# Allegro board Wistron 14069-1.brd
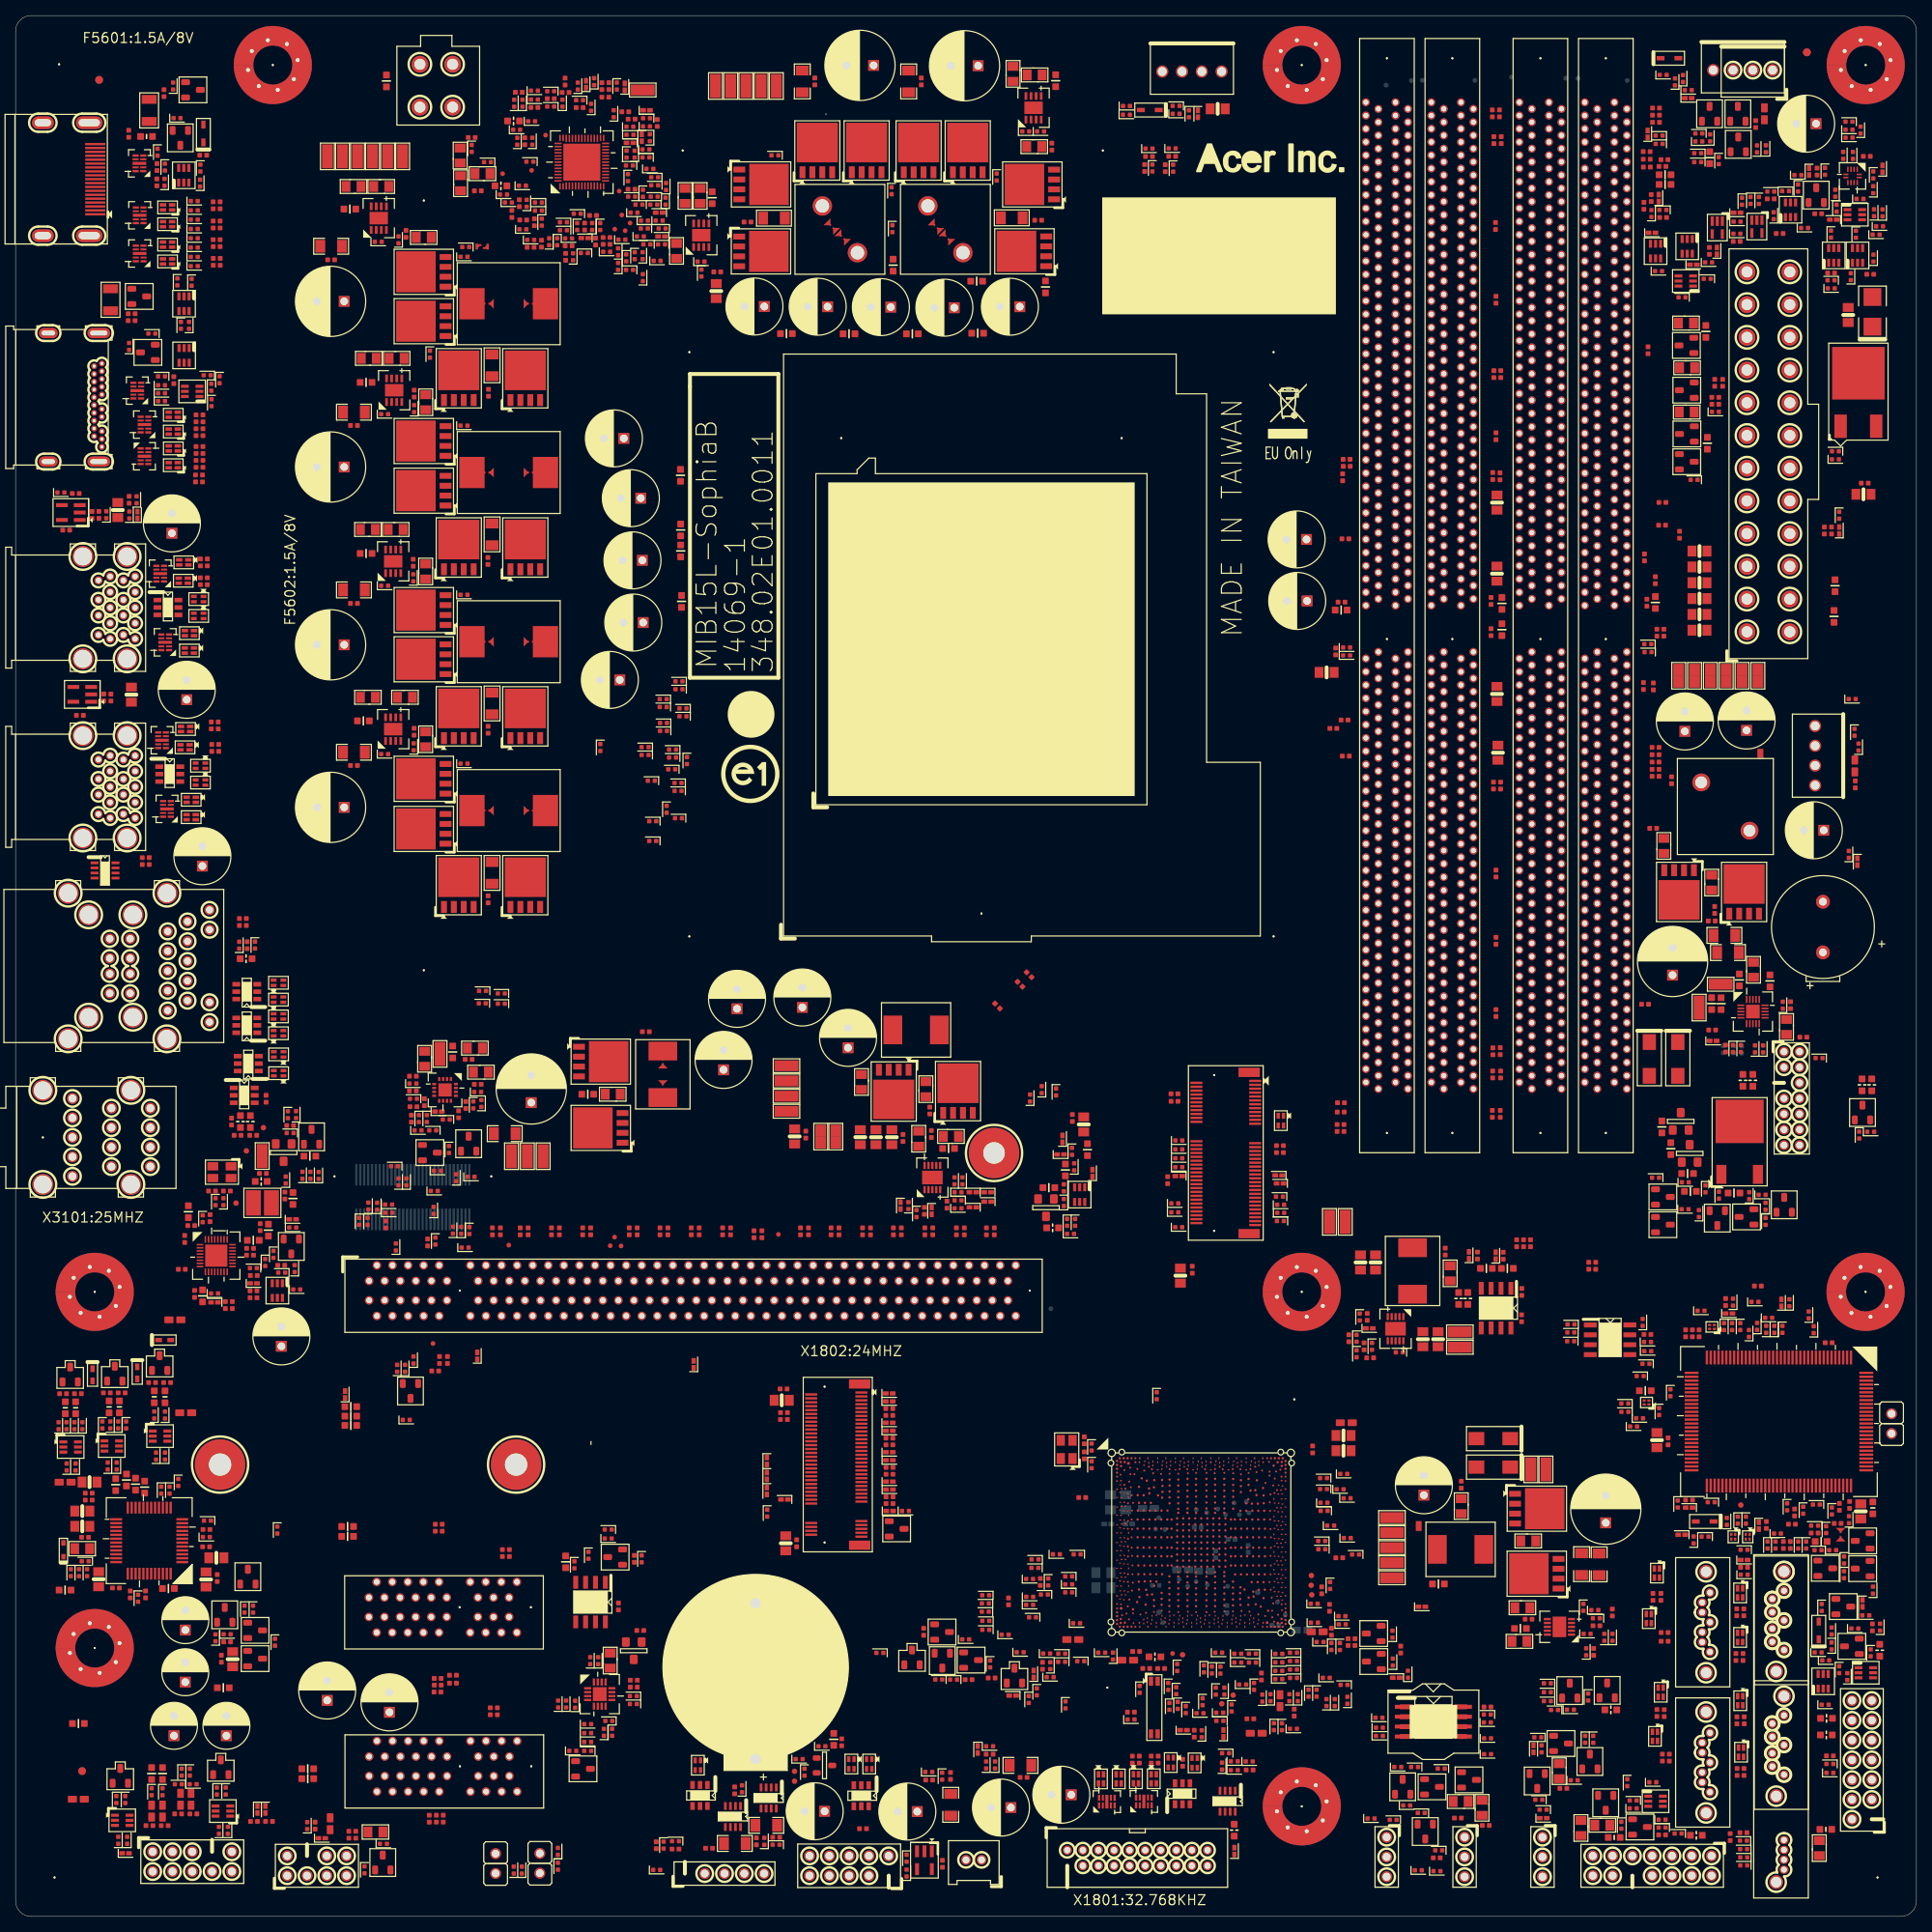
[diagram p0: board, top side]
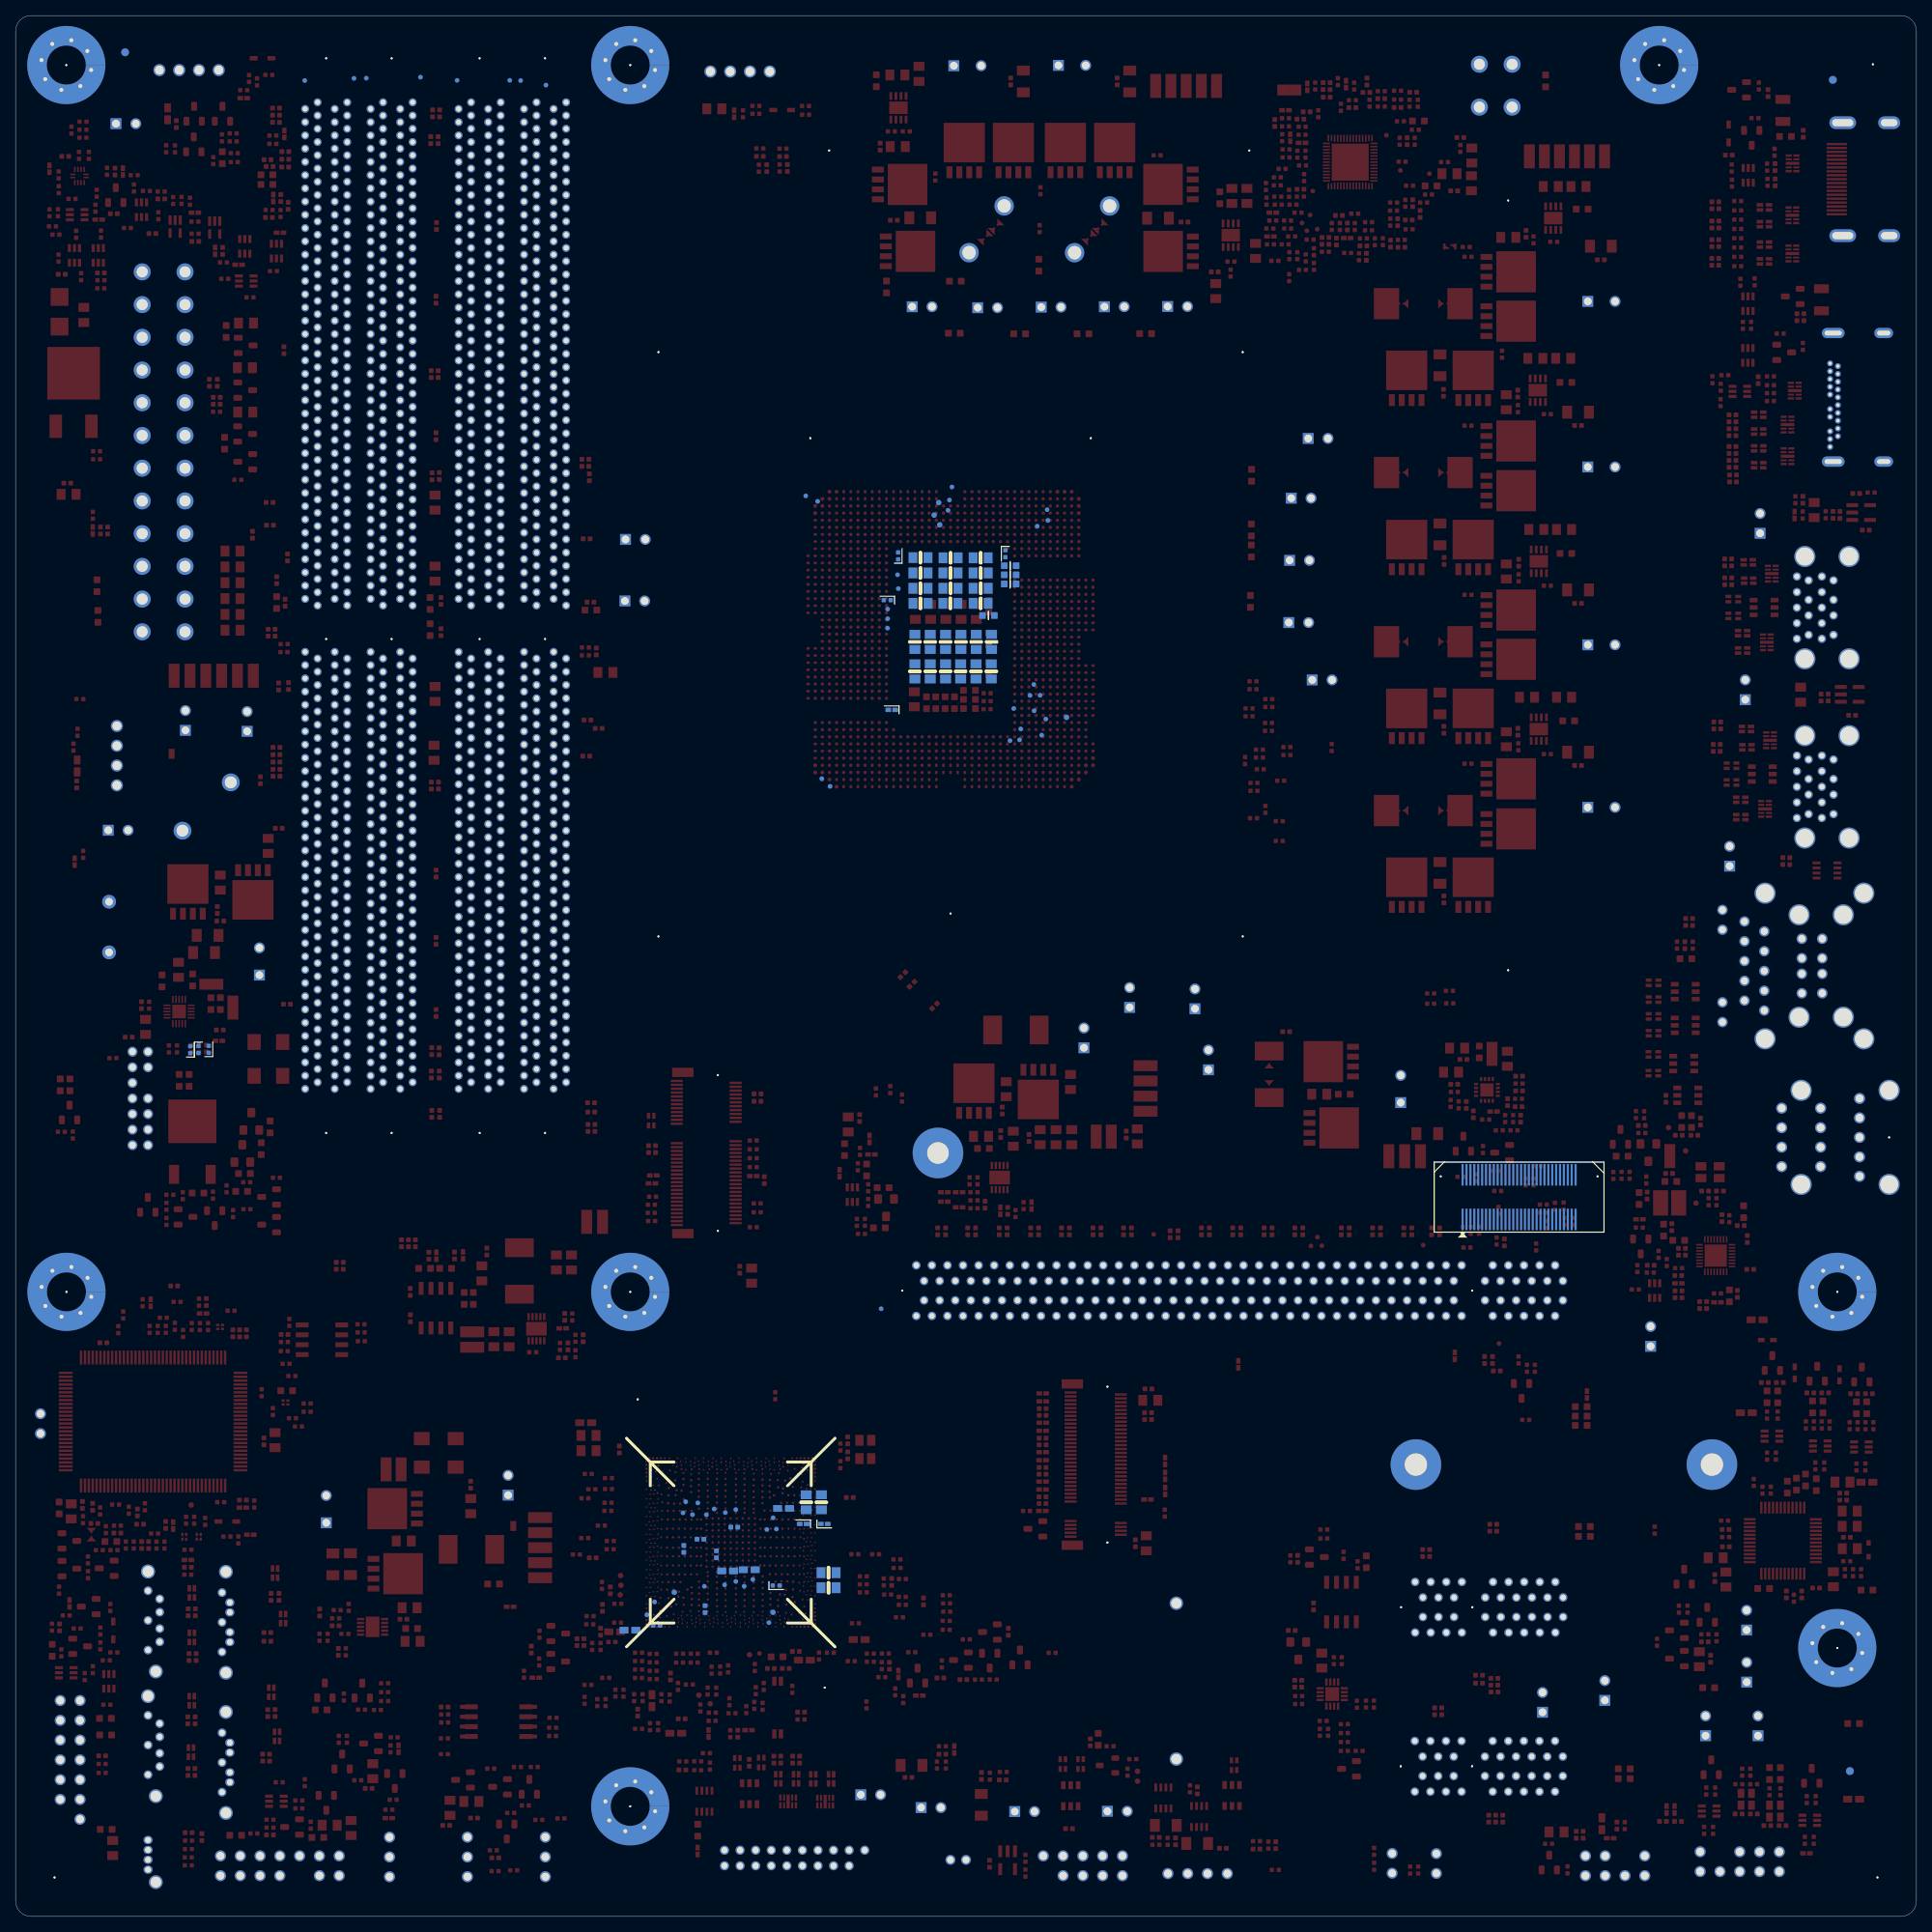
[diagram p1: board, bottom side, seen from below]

Outline 244 x 244 mm; copper layers: TOP, L2, L3, BOTTOM. Coordinates in mm from the lower left corner of the outline.
Outline path: 0,242 0,2 arc(0.59,0.59) 2,0 242,0 arc(243.41,0.59) 244,2 244,242 arc(243.41,243.41) 242,244 2,244 arc(0.59,243.41) 0,242

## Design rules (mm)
constraint set DEFAULT: min track width 0.127, pair gap 0.102
net group DP_AUX_CON_N: nets DP_AUX_CPU_N DP_AUX_CPU_N_C
net group DP_AUX_CON_P: nets DP_AUX_CPU_P DP_AUX_CPU_P_C
net group DP_DATA_CON_N0: nets DP_DATA_CPU_N0 DP_DATA_N0
net group DP_DATA_CON_N1: nets DP_DATA_CPU_N1 DP_DATA_N1
net group DP_DATA_CON_N2: nets DP_DATA_CPU_N2 DP_DATA_N2
net group DP_DATA_CON_N3: nets DP_DATA_CPU_N3 DP_DATA_N3
net group DP_DATA_CON_P0: nets DP_DATA_CPU_P0 DP_DATA_P0
net group DP_DATA_CON_P1: nets DP_DATA_CPU_P1 DP_DATA_P1
net group DP_DATA_CON_P2: nets DP_DATA_CPU_P2 DP_DATA_P2
net group DP_DATA_CON_P3: nets DP_DATA_CPU_P3 DP_DATA_P3
net group FAN_SYS_POWER: nets SYS_FAN_3P_POWER SYS_FAN_3P_POWER_2
net group HDA_BITCLK_CODEC: nets HDA_BITCLK_CODEC HDA_BITCLK_PCH
net group HDA_RST#_CODEC: nets HDA_RST#_CODEC HDA_RST#_PCH
net group HDA_SDIN0_CODEC: nets HDA_SDIN0_CODEC HDA_SDIN0_PCH
net group HDA_SDOUT_CODEC: nets HDA_SDOUT_CODEC HDA_SDOUT_PCH
net group HDA_SYNC_CODEC: nets HDA_SYNC_CODEC HDA_SYNC_PCH
net group HDMI_CLK_CON: nets HDMI_CLK_CON HDMI_CLK_PCH
net group HDMI_DATA_CMC_N0: nets HDMI_DATA_CMC_N0 HDMI_DATA_CPU_N0
net group HDMI_DATA_CMC_N1: nets HDMI_DATA_CMC_N1 HDMI_DATA_CPU_N1
net group HDMI_DATA_CMC_N2: nets HDMI_DATA_CMC_N2 HDMI_DATA_CPU_N2
net group HDMI_DATA_CMC_N3: nets HDMI_DATA_CMC_N3 HDMI_DATA_CPU_N3
net group HDMI_DATA_CMC_P0: nets HDMI_DATA_CMC_P0 HDMI_DATA_CPU_P0
net group HDMI_DATA_CMC_P1: nets HDMI_DATA_CMC_P1 HDMI_DATA_CPU_P1
net group HDMI_DATA_CMC_P2: nets HDMI_DATA_CMC_P2 HDMI_DATA_CPU_P2
net group HDMI_DATA_CMC_P3: nets HDMI_DATA_CMC_P3 HDMI_DATA_CPU_P3
net group HDMI_DATA_CON: nets HDMI_DATA_CON HDMI_DATA_PCH
net group HDMI_DDSP_D: nets DDSP_D_TX_N0 DDSP_D_TX_N2
net group LAN_MDI_CON_N0: nets LAN_MDI_CON_N0 LAN_MDI_LAN_N0
net group LAN_MDI_CON_N1: nets LAN_MDI_CON_N1 LAN_MDI_LAN_N1
net group LAN_MDI_CON_N2: nets LAN_MDI_CON_N2 LAN_MDI_LAN_N2
net group LAN_MDI_CON_N3: nets LAN_MDI_CON_N3 LAN_MDI_LAN_N3
net group LAN_MDI_CON_P0: nets LAN_MDI_CON_P0 LAN_MDI_LAN_P0
net group LAN_MDI_CON_P1: nets LAN_MDI_CON_P1 LAN_MDI_LAN_P1
net group LAN_MDI_CON_P2: nets LAN_MDI_CON_P2 LAN_MDI_LAN_P2
net group LAN_MDI_CON_P3: nets LAN_MDI_CON_P3 LAN_MDI_LAN_P3
net group PCIE_RX_CON_N9: nets PCIE_RX_CON_N9 PCIE_RX_PCH_N9
net group PCIE_RX_CON_N10: nets PCIE_RX_CON_N10 PCIE_RX_PCH_N10
net group PCIE_RX_CON_N11: nets PCIE_RX_CON_N11 PCIE_RX_PCH_N11
net group PCIE_RX_CON_P9: nets PCIE_RX_CON_P9 PCIE_RX_PCH_P9
net group PCIE_RX_CON_P10: nets PCIE_RX_CON_P10 PCIE_RX_PCH_P10
net group PCIE_RX_CON_P11: nets PCIE_RX_CON_P11 PCIE_RX_PCH_P11
net group PCIE_RX_LAN_N5: nets PCIE_RX_LAN_N5 PCIE_RX_PCH_N5
net group PCIE_RX_LAN_P5: nets PCIE_RX_LAN_P5 PCIE_RX_PCH_P5
net group PCIE_TX_CON_N6: nets PCIE_TX_CON_N6 PCIE_TX_PCH_N6
net group PCIE_TX_CON_N7: nets PCIE_TX_CON_N7 PCIE_TX_PCH_N7
net group PCIE_TX_CON_N8: nets PCIE_TX_CON_N8 PCIE_TX_PCH_N8
net group PCIE_TX_CON_N9: nets PCIE_TX_CON_N9 PCIE_TX_PCH_N9
net group PCIE_TX_CON_N10: nets PCIE_TX_CON_N10 PCIE_TX_PCH_N10
net group PCIE_TX_CON_N11: nets PCIE_TX_CON_N11 PCIE_TX_PCH_N11
net group PCIE_TX_CON_N12: nets PCIE_TX_CON_N12 PCIE_TX_PCH_N12
net group PCIE_TX_CON_P6: nets PCIE_TX_CON_P6 PCIE_TX_PCH_P6
net group PCIE_TX_CON_P7: nets PCIE_TX_CON_P7 PCIE_TX_PCH_P7
net group PCIE_TX_CON_P8: nets PCIE_TX_CON_P8 PCIE_TX_PCH_P8
net group PCIE_TX_CON_P9: nets PCIE_TX_CON_P9 PCIE_TX_PCH_P9
net group PCIE_TX_CON_P10: nets PCIE_TX_CON_P10 PCIE_TX_PCH_P10
net group PCIE_TX_CON_P11: nets PCIE_TX_CON_P11 PCIE_TX_PCH_P11
net group PCIE_TX_CON_P12: nets PCIE_TX_CON_P12 PCIE_TX_PCH_P12
net group PCIE_TX_LAN_N5: nets PCIE_TX_LAN_N5 PCIE_TX_PCH_N5
net group PCIE_TX_LAN_P5: nets PCIE_TX_LAN_P5 PCIE_TX_PCH_P5
net group PEG_RCOMP: nets PEG_RCOMPN_CPU PEG_RCOMPP_CPU
net group PEG_TX_CON_N0: nets PEG_TX_CON_N0 PEG_TX_CPU_N0
net group PEG_TX_CON_N1: nets PEG_TX_CON_N1 PEG_TX_CPU_N1
net group PEG_TX_CON_N2: nets PEG_TX_CON_N2 PEG_TX_CPU_N2
net group PEG_TX_CON_N3: nets PEG_TX_CON_N3 PEG_TX_CPU_N3
net group PEG_TX_CON_N4: nets PEG_TX_CON_N4 PEG_TX_CPU_N4
net group PEG_TX_CON_N5: nets PEG_TX_CON_N5 PEG_TX_CPU_N5
net group PEG_TX_CON_N6: nets PEG_TX_CON_N6 PEG_TX_CPU_N6
net group PEG_TX_CON_N7: nets PEG_TX_CON_N7 PEG_TX_CPU_N7
net group PEG_TX_CON_N8: nets PEG_TX_CON_N8 PEG_TX_CPU_N8
net group PEG_TX_CON_N9: nets PEG_TX_CON_N9 PEG_TX_CPU_N9
net group PEG_TX_CON_N10: nets PEG_TX_CON_N10 PEG_TX_CPU_N10
net group PEG_TX_CON_N11: nets PEG_TX_CON_N11 PEG_TX_CPU_N11
net group PEG_TX_CON_N12: nets PEG_TX_CON_N12 PEG_TX_CPU_N12
net group PEG_TX_CON_N13: nets PEG_TX_CON_N13 PEG_TX_CPU_N13
net group PEG_TX_CON_N14: nets PEG_TX_CON_N14 PEG_TX_CPU_N14
net group PEG_TX_CON_N15: nets PEG_TX_CON_N15 PEG_TX_CPU_N15
net group PEG_TX_CON_P0: nets PEG_TX_CON_P0 PEG_TX_CPU_P0
net group PEG_TX_CON_P1: nets PEG_TX_CON_P1 PEG_TX_CPU_P1
net group PEG_TX_CON_P2: nets PEG_TX_CON_P2 PEG_TX_CPU_P2
net group PEG_TX_CON_P3: nets PEG_TX_CON_P3 PEG_TX_CPU_P3
net group PEG_TX_CON_P4: nets PEG_TX_CON_P4 PEG_TX_CPU_P4
net group PEG_TX_CON_P5: nets PEG_TX_CON_P5 PEG_TX_CPU_P5
net group PEG_TX_CON_P6: nets PEG_TX_CON_P6 PEG_TX_CPU_P6
net group PEG_TX_CON_P7: nets PEG_TX_CON_P7 PEG_TX_CPU_P7
net group PEG_TX_CON_P8: nets PEG_TX_CON_P8 PEG_TX_CPU_P8
net group PEG_TX_CON_P9: nets PEG_TX_CON_P9 PEG_TX_CPU_P9
net group PEG_TX_CON_P10: nets PEG_TX_CON_P10 PEG_TX_CPU_P10
net group PEG_TX_CON_P11: nets PEG_TX_CON_P11 PEG_TX_CPU_P11
net group PEG_TX_CON_P12: nets PEG_TX_CON_P12 PEG_TX_CPU_P12
net group PEG_TX_CON_P13: nets PEG_TX_CON_P13 PEG_TX_CPU_P13
net group PEG_TX_CON_P14: nets PEG_TX_CON_P14 PEG_TX_CPU_P14
net group PEG_TX_CON_P15: nets PEG_TX_CON_P15 PEG_TX_CPU_P15
net group POWER_80_12: nets 5V_AUX_WPWR PWR_2D5V_PVIN
net group PWR_RT3607_RGNDA: nets PWR_RT3607_RGNDA VSSGT_SENSE
net group PWR_VCCSA_FB: nets PWR_VCCSA_FB VCCSA_SENSE
net group SIO_VREF: nets SYS_TMPIN VRD_TMPIN
net group SPI_CLK_PCH: nets SPI_CLK_PCH SPI_CLK_ROM
net group SPI_HOLD_PCH: nets SPI_HOLD_PCH SPI_HOLD_ROM
net group SPI_S: nets SPI_CS_PCH_N0 SPI_WP_ROM_PLL
net group SPI_SI_PCH: nets SPI_SI_PCH SPI_SI_ROM
net group SPI_SO_PCH: nets SPI_SO_PCH SPI_SO_ROM
net group USB30_RX_CON_N1: nets USB30_RX_CON_N1 USB30_RX_PCH_N1
net group USB30_RX_CON_N2: nets USB30_RX_CON_N2 USB30_RX_PCH_N2
net group USB30_RX_CON_N3: nets USB30_RX_CON_N3 USB30_RX_PCH_N3
net group USB30_RX_CON_N4: nets USB30_RX_CON_N4 USB30_RX_PCH_N4
net group USB30_RX_CON_N5: nets USB30_RX_CON_N5 USB30_RX_PCH_N5
net group USB30_RX_CON_N6: nets USB30_RX_CON_N6 USB30_RX_PCH_N6
net group USB30_RX_CON_P1: nets USB30_RX_CON_P1 USB30_RX_PCH_P1
net group USB30_RX_CON_P2: nets USB30_RX_CON_P2 USB30_RX_PCH_P2
net group USB30_RX_CON_P3: nets USB30_RX_CON_P3 USB30_RX_PCH_P3
net group USB30_RX_CON_P4: nets USB30_RX_CON_P4 USB30_RX_PCH_P4
net group USB30_RX_CON_P5: nets USB30_RX_CON_P5 USB30_RX_PCH_P5
net group USB30_RX_CON_P6: nets USB30_RX_CON_P6 USB30_RX_PCH_P6
net group USB_CON_PN1: nets USB_CON_PN1 USB_PCH_PN1
net group USB_CON_PN2: nets USB_CON_PN2 USB_PCH_PN2
net group USB_CON_PN3: nets USB_CON_PN3 USB_PCH_PN3
net group USB_CON_PN4: nets USB_CON_PN4 USB_PCH_PN4
net group USB_CON_PN5: nets USB_CON_PN5 USB_PCH_PN5
net group USB_CON_PN6: nets USB_CON_PN6 USB_PCH_PN6
net group USB_CON_PN7: nets USB_CON_PN7 USB_PCH_U_PN7
net group USB_CON_PN8: nets USB_CON_PN8 USB_PCH_PN8
net group USB_CON_PN9: nets USB_CON_PN9 USB_PCH_PN9
net group USB_CON_PN10: nets USB_CON_PN10 USB_PCH_PN10
net group USB_CON_PN11: nets USB_CON_PN11 USB_PCH_PN11
net group USB_CON_PN12: nets USB_CON_PN12 USB_PCH_PN12
net group USB_CON_PP1: nets USB_CON_PP1 USB_PCH_PP1
net group USB_CON_PP2: nets USB_CON_PP2 USB_PCH_PP2
net group USB_CON_PP3: nets USB_CON_PP3 USB_PCH_PP3
net group USB_CON_PP4: nets USB_CON_PP4 USB_PCH_PP4
net group USB_CON_PP5: nets USB_CON_PP5 USB_PCH_PP5
net group USB_CON_PP6: nets USB_CON_PP6 USB_PCH_PP6
net group USB_CON_PP7: nets USB_CON_PP7 USB_PCH_U_PP7
net group USB_CON_PP8: nets USB_CON_PP8 USB_PCH_PP8
net group USB_CON_PP9: nets USB_CON_PP9 USB_PCH_PP9
net group USB_CON_PP10: nets USB_CON_PP10 USB_PCH_PP10
net group USB_CON_PP11: nets USB_CON_PP11 USB_PCH_PP11
net group USB_CON_PP12: nets USB_CON_PP12 USB_PCH_PP12
net group ATX_EN: nets BV_PS_ON_HEADER_N
net group AUDIO_AIO_50R: nets AUD_IN_L AUD_IN_LL AUD_IN_LL_1 AUD_IN_R AUD_IN_RR AUD_IN_RR_1 AUD_MIC1_L AUD_MIC1_LL AUD_MIC1_LL_1 AUD_MIC1_R AUD_MIC1_RR AUD_MIC1_RR_1 AUD_MIC_1L AUD_MIC_1R AUDAMPIN_L AUDAMPIN_L_C AUDAMPIN_R AUDAMPIN_R_C AUDIN_L AUDIN_R BZ_ON BZ_ON1 FB_AUDOUT_L FB_AUDOUT_R FB_AUDOUTR_L FB_AUDOUTR_R FP_MIC2_L FP_MIC2_L_C FP_MIC2_R FP_MIC2_R_C FP_OUT_L FP_OUT_L_C FP_OUT_R FP_OUT_R_C FP_OUTR_L FP_OUTR_LL FP_OUTR_R FP_OUTR_RR FP_OUTR_SENSE LINE_SPK_L LINE_SPK_R MIC2_L MIC2_LL MIC2_R MIC2_RR MONO_C_L MONO_C_R MONO_L MONO_R PCH_SPKR1 SPKR
net group AUDIO_AZACPU: nets AUD_AZACPU_CPU_SDI AUD_AZACPU_SCLK AUD_AZACPU_SCLK_R AUD_AZACPU_SDI AUD_AZACPU_SDO AUD_AZACPU_SDO_R
net group AUDIO_HDA: nets HDA_RST#_CODEC_R HDA_SDOUT_PCH_R1 HDA_SDOUT_PCH_R2
net group AUDIO_IO_POP_50R: nets 3.3_POP ANTI-POP_GPIO1 ANTI-POP_GPIO1_L ANTI-POP_GPIO1_R AUD_IN_LL* AUD_IN_RR* AUD_MIC1_LL* AUD_MIC1_RR* EAPD_DEPOP FB_AUDOUTR_L* FB_AUDOUTR_R* FP_AUDIO_PRESENCE*_C FP_AUDIO_PRESENCE_N FP_OUT_LL* FP_OUT_RR* MIC2_LL* MIC2_RR* MUTE MUTE_C MUTE_INT MUTE_R MUTE_RR
net group AUDIO_SENSE: nets FRONT_JD LINE2_JD LINEIN_JD MIC1_JD MIC2_JD SENSE_A SENSE_B
net group AUDIO_VREF: nets FP_MICVREF_D1 FP_MICVREF_D2 JDREF LINE2_VREFO LINE2_VREFO_D1 LINE2_VREFO_D2 MIC1_VREFO_L MIC1_VREFO_R MIC2-VREFO
net group AUDIO_VREF1: nets AVDD2
net group AUDIO_VREF2: nets AUDIO_VREF
net group CFG_RCOMP: nets CFG_RCOMP
net group CLK: nets BLAN_XTALI BLAN_XTALO BLAN_XTALO_1 CLK_CLKIN_SIO CLK_LPC_PORT80 CLK_LPC_PORT80_R CLK_PCICLK_SIO CLK_PCICLK_SIO_R CLKOUT_48M_R PCH_SUSCLK_WLAN SUSCLK_PCH_M2
net group CPU_MS_4_8: nets PM_DOWN_CPU PM_DOWN_PCH PM_SYNC_CPU PM_SYNC_PCH PROC_TRIGIN_CPU PROC_TRIGIN_PCH PROC_TRIGOUT_CPU PROC_TRIGOUT_PCH
net group CPU_MS_4_12: nets H_SKTOCC_N PCH_HOT_R_N PCH_INTRUDER_N PROCHOT#_CPU PROCHOT#_R THERMTRIP#_CPU_R THERMTRIP#_PCH
net group CPUXDP: nets BPM_CPU_N0 BPM_CPU_N1 CFG0 CFG1 CFG2 CFG3 CFG4 CFG5 CFG6 CFG7 CFG8 CFG9 CFG10 CFG11 CFG12 CFG13 CFG14 CFG15 CPU_VCCST_PWRGD_Q_PLL H_PRDY_N H_PRDY_PCH H_PREQ_N H_PREQ_PCH H_TCK H_TDI H_TDO H_TMS H_TRST_N H_TRST_N_R PRIM_XDP_JTAG_TCK_R SKL_PCUSTB_0_DN SKL_PCUSTB_0_DP SKL_PCUSTB_1_DN SKL_PCUSTB_1_DP XDP_HOOK0 XDP_HOOK1 XDP_HOOK2 XDP_HOOK3 XDP_HOOK6 XDP_PCUDEBUG3
net group DIMM_MISC: nets EVENT#1 EVENT#2 EVENT#3 EVENT#4 M_ALERT_A_N M_ALERT_B_N
net group DIMM_VREF: nets DIMM_CA_CPU_VREF_A_RC DIMM_CA_VREF_A DIMM_CA_VREF_B DIMM_DQ_CPU_VREF_B_RC DIMM_DQ_VREF_B M_VREF_DQ_DIM1 V_SM_R2_DIMM_VREF_A
net group DIMM_VREF_1: nets V_SM_VREF_CNT
net group DISPLAY_CTRL_CLK_DATA: nets DDPD_CTRLCLK_PCH DDPD_CTRLDATA_PCH DP_CTRLCLK_PCH DP_CTRLDATA_PCH
net group DISPLAY_HPD_SIGNALS: nets DP_HPD_CON DP_HPD_PCH EDP_HPD_PD HDMI_DET_CON HDMI_DET_PCH HDMI_Q64_PIN5 Q64_PIN2
net group E_POWER_10_10: nets 5V_DDCHDMI_S0 5V_HDMICON_S0 5V_HDMICON_S0_L CORE_GAP1 CORE_GAP2 CORE_GAP3 CORE_GAP4 CSN4 CSP4 DISCHARGE_A DISCHARGE_B DISCHARGE_C DISCHARGE_M PWM4 PWR_+0P95V_CS PWR_+0P95V_EN PWR_+0P95V_RF PWR_+PCH_1V0_CS PWR_+PCH_1V0_FB PWR_+PCH_1V0_FB1 PWR_+PCH_1V0_PG PWR_+PCH_1V0_RF PWR_VDDQ_DDR_CS PWR_VDDQ_DDR_FB PWR_VDDQ_DDR_FB1 PWR_VDDQ_DDR_TON PWR_VDDQ_DDR_VTTREF PWRGD3V_150MS RTCEXT_CAP SIO_VCC_BLEED VCCGT_GAP1 VCCGT_GAP2
net group E_POWER_20_10: nets 1V_VCCAMPHYPLL_S5 1V_VCCAPLL_S5 1V_VCCDSW_PCH 1V_VCCF24_S5 3D3V_DPPWR_S0 3D3V_DPPWR_S0_F 3D3V_DVDDIO_AUDIO 3D3V_VCCPRTC 3D3V_VDDREGIN_LAN 3V_VBAT1_G3 3V_VBAT1_G3_R 5V_RR +VCCFUSEPRG +VCCPLL_OC_R PWR_+0P95V_BOOT PWR_+0P95V_BOOT_R PWR_+0P95V_SNB PWR_+0P95V_VCC PWR_+0P95V_VIN PWR_+PCH_1V0 PWR_+PCH_1V0_BOOT PWR_+PCH_1V0_BOOT1 PWR_+PCH_1V0_SNB PWR_VCCSA_SNB PWR_VCCSA_VIN PWR_VDDQ_DDR_BOOT PWR_VDDQ_DDR_LDOIN PWR_VDDQ_DDR_SNB SIO_AVCC3 SIO_MAIN_VCC3 V_3P3_DBP V_CPU_ST_PLL_R VBAT_SIO VCC_ST
net group E_POWER_30_8: nets 3D3V_1D8V_PCHSPI_S5 3D3V_VCCPGPPA_S5 3D3V_VCCPGPPD_S5 LAN_CONN_CVT
net group E_POWER_40_10: nets 1D05V_VLAN 1D05V_VLANOUT 1V_PRIME_PCH_FUSE_SX 2D5V_VPP_S3 3D3V_LAN 3D3V_SB 3D3V_VCCPRIM 3V_BATIN_SX 3V_VRTC_G3 +PWR_DDR_VTT OPC_FUSEPRG PWR_2D5V_VPP PWR_+0P95V SYS_3VSB VCC3_3SBREF VCC_EOPIO VCC_GTX VCC_OPC VCC_OPC_DP8
net group E_POWER_50_H: nets 5V_DUAL_USB_F 5V_DUAL_USBCHAR_F 5V_S0 5V_USB20_RJUSB 5V_USB20H2 5V_USB20H3 5V_USB30H1 5V_USB30P1 5V_USB30P2
net group E_POWER_100_10: nets 0D6V_VTT 0D95V_VCCIO_S0 0D95V_VCCSA_S0 1D2V_VDDQ_S3 1V_CPU_CORE 1V_S5 1V_VCCGT_S0 3D3V_S0 3D3V_S5 5V_LDOIN_SIO_SX PWR_2D5V_LX
net group E_POWER_100_H: nets 5V_AUX 5V_SB 12V_CPU_S0 12V_S0 -12V_S0 PCH_POWER_VIN
net group EDP_RCOMP: nets EDP_RCOMP_CPU
net group EN_PG_RST_4_10: nets CLK_REQ_SATA_N CMOS1_3 DEVSLP FP_RST_N IMVP8_EN_R ME_CNTL MINI1_WAKE# NGFFE_ALERT# NGFFE_ALERT#_R OCL_PCH_N PB_IN_N_1 PCH_GPIO1 PCH_GPIO2 PCH_PORT80_LED PCH_WAKE_N PEG_CLKREQ1_WLAN# PEG_CLKREQ2_LAN# PEG_CLKREQ3_M2# PEG_PCIEX1_CLKREQ5 PEG_PCIEX1_CLKREQ6 PLT_WLAN_RST_C PLTRST#_PCH PLTRST_CPU_N PS_ON_N PWR_BTNJ_C PWRDOWN_Q SIO_EUP_EN SLP_A# SLP_LAN_N SLP_S3_A SLP_S3_B SLP_S4_N_SFR SLP_S4_N_SFR_1 SLP_S4_N_SFR_2 SLP_S4_N_SFR_G SLP_WLAN_N SPI_WP_HW SPI_WP_ROM_C SPI_WP_ROM_C2 SUS_STAT_N SW_ON_N_SIO U498_GATE VDDQ_R VPP_R VRMPWG_G VRMPWG_G_R W1_DISABLE_N
net group EN_PG_RST_4_15: nets ATX_PWRGD_A CPU_VCCST_PWRGD CPU_VCCST_PWRGD_Q DPWROK H_PWRGD H_PWRGD_PCH H_TRST_N_X LAN_WAKE_N LAN_WAKEB ME_CNTL_1 ME_CNTL_2 PCH_PWROK PCH_SYSPWROK PCIEX16_PRSNT2_N PCIEX16_PRSNT2_R1_N PCIEX16_PRSNT2_R2_N PLTRST#_PCH_R PLTRST#_R PLTRST_LAN_N PLTRST_LAN_N_R PWRGD_PS RSMRST_SIO_N S3_VTT_CTNL SLP_S3_N SLP_S4_N SLP_SUS_N SM_DRAMRST# SM_DRAMRST#_R SW_ON_N VCCIO_EN_C VCCIO_EN_R VCCIO_PWRGD VCORE_PG VDDQ_EN_R VPP_EN_R VPP_PG VR_ENABLE VTT_EN_R W3_DISABLE_N
net group EN_SEQUENCE_4_10: nets BLEED BLEED_EN DDR_VTT_CNTL_CPU DDR_VTT_CNTL_R S4_VPP_OR S4_VPP_OR_R SLP_S4_N_R VDDQ_EN_CR VPP_EN_CR VPP_EN_DDR4 VTT_A VTT_B VTT_EN_CR
net group FAN_CPU_CTRL: nets CPU_FAN_CTRL_CONN CPU_FAN_PWM1 CPU_FAN_TACH1 CPU_FAN_TACH_1 CPU_FAN_TACH_L
net group FAN_SYS_CTRL: nets SYS_FAN_3P_G SYS_FAN_3P_G2 SYS_FAN_FB SYS_FAN_FB2 SYS_FAN_M SYS_FAN_M1 SYS_FAN_M2 SYS_FAN_M12 SYS_FAN_PWM1 SYS_FAN_PWM2 SYS_FAN_TACH1 SYS_FAN_TACH1_1 SYS_FAN_TACH1_2 SYS_FAN_TACH2 SYS_FAN_TACH2_1 SYS_FAN_TACH2_2 SYSTEM_FAN_PWM1_1 SYSTEM_FAN_PWM1_2 SYSTEM_FAN_PWM1_3 SYSTEM_FAN_PWM2_1 SYSTEM_FAN_PWM2_2 SYSTEM_FAN_PWM2_3
net group GND: nets AGND ESDGND GND SIO_AGND
net group HVID: nets VIDALERT#_CPU VIDALERT#_VR1 VIDSCK_CPU VIDSCK_VR1 VIDSOUT_CPU VIDSOUT_VR1
net group LAN_CTRL_4_5: nets LAN_EN_1 LAN_EN_2 LAN_EN_3 LAN_RSET
net group LAN_CTRL_4_10: nets LAN_DISABLE_N LAN_ISOLATE_N LANCLK_REQ_N_R RTL_ISOLATE RTL_ISOLATE_R SLP_LAN_N_C
net group LAN_LED: nets LAN_LINKACTIVITY_CON_N LAN_LINKACTIVITY_LAN_N LAN_SPEED100_CON_N LAN_SPEED100_LAN_N LAN_SPEED1000_CON_N LAN_SPEED1000_LAN_N
net group LED: nets HD_LED_PWR LAN_LED* LAN_LED*_EMI LAN_LEDC0 OC_LED_GREEN_C PWR_LED_G PWR_LED_T PWR_LED_YELLOW_C PWR_LED_YELLOW_C2 PWR_LEDJ_C PWR_LEDJ_G PWR_LEDJ_P PWR_LEDJ_T PWRLED_2 SATA_LED_OUT V_5_PWR1
net group LED_CTRL: nets LAN_LEDC1 LAN_LEDC1_E PCH_SATA_LED_N PCH_SATA_LED_NMOS PCH_SATA_LED_R_N PWR_LEDC1 PWR_LEDC1_D PWR_LEDC2 PWR_LEDC2_D PWR_LEDC3 SIO_OCL_GREEN_R SIO_PWM_LED_N
net group LPC: nets LPC_AD_SIO_P0 LPC_AD_SIO_P1 LPC_AD_SIO_P2 LPC_AD_SIO_P3 LPC_FRAME#_SIO LPC_PME_N LPC_PME_N_PCH LPC_PRIQ LPC_SERIRQ_PCH
net group M2_CTRL: nets HPGP_M2_SATA_DET# M2_CLKREQ# M2_PERST# M2_SATA_DET_PCH M2_WAKE# SSD_SATA_DEVSLP
net group MINI_CARD: nets MINI_CLKREQ#_WLAN_C
net group MISC_4_5: nets BATLOW_N BOARD_ID_0 BOARD_ID_1 BOARD_ID_2 GPD1 GPP_C_5 GPP_H_12 PCH_CLKRUN_N USB2_ID VRALERTB_PU
net group MISC_4_8: nets DP1_PWR_CTRL DP_DEVICE_DETECT DP_DONGLE_DET HDMI_DEVICE_DETECT LPSS_GSPI0_MOSI LPSS_GSPI1_MOSI PCIEX16_PRSNT1_N VISACH2_D3
net group OTHER_4: nets DP1_14
net group PCH_JTAG: nets ITP_PMODE PCH_JTAG_TCK PCH_JTAG_TDI PCH_JTAG_TDO PCH_JTAG_TMS PCH_JTAGX
net group PM_PTM: nets PECI_CPU PECI_PCH PECI_SIO_R
net group PWM_10_10: nets CSN1 CSN1A CSN2 CSN2A CSN3 CSP1 CSP1A CSP2 CSP2A CSP3 PWR_RT3607_ALTER PWR_RT3607_COMP PWR_RT3607_COMP_L PWR_RT3607_COMPA PWR_RT3607_COMPA_L PWR_RT3607_DVD PWR_RT3607_FB PWR_RT3607_FB2_C PWR_RT3607_FBA PWR_RT3607_FBA2_C PWR_RT3607_IBIAS PWR_RT3607_IMON PWR_RT3607_IMONA PWR_RT3607_ISEN1N PWR_RT3607_ISEN2N PWR_RT3607_ISEN3N PWR_RT3607_ISEN4N PWR_RT3607_ISENA1N PWR_RT3607_ISENA2N PWR_RT3607_ISENA3N PWR_RT3607_PS4 PWR_RT3607_SET1 PWR_RT3607_SET1_N PWR_RT3607_SET1_N# PWR_RT3607_SET2 PWR_RT3607_SET2_N PWR_RT3607_SET2_N# PWR_RT3607_SET3 PWR_RT3607_SET3_N PWR_RT3607_SET3_N# PWR_RT3607_SETA1 PWR_RT3607_SETA1_N PWR_RT3607_SETA1_N# PWR_RT3607_SETA2 PWR_RT3607_SETA2_N PWR_RT3607_SETA2_N# PWR_RT3607_TONSET PWR_RT3607_TONSET_R PWR_RT3607_TONSETA PWR_RT3607_TONSETA_R PWR_RT3607_TSEN PWR_RT3607_TSEN_R1 PWR_RT3607_TSEN_R2 PWR_RT3607_TSENA PWR_RT3607_TSENA_R1 PWR_RT3607_TSENA_R2 PWR_RT3607_VCLK PWR_RT3607_VDIO PWR_RT3607_VREF PWR_RT3607_VREF_1 PWR_RT3607_VREF_2 PWR_RT3607_VREF_3 PWR_RT3607_VREF_4 PWR_RT3607_VREF_5 PWR_RT3607_VREF_6 PWR_RT3607_VREF_R PWRBTN_N RT3607_PS4_RIGHTLINE
net group PWM_10_20: nets PWM1 PWM1A PWM2 PWM2A PWM3 PWR_2D5V_FB PWR_2D5V_FB_N PWR_VCCSA_COMP PWR_VCCSA_COMP_A PWR_VCCSA_COMP_R PWR_VCCSA_CSN PWR_VCCSA_CSP PWR_VCCSA_CSP_R PWR_VCCSA_VSEN
net group PWM_20_10: nets PWR_+PCH_1V0_VCC PWR_+PCH_1V0_VIN PWR_RT3607_VCC PWR_RT9624F_BST1 PWR_RT9624F_BST1A PWR_RT9624F_BST1AR PWR_RT9624F_BST1R PWR_RT9624F_BST2 PWR_RT9624F_BST2A PWR_RT9624F_BST2AR PWR_RT9624F_BST2R PWR_RT9624F_BST3R PWR_RT9624F_BST4R PWR_VCCSA_VCC PWR_VCCSA_VCCP PWR_VDDQ_DDR_VDD PWR_VDDQ_DDR_VDDQ PWR_VDDQ_DDR_VIN
net group PWM_20_20: nets PWR_2D5V_SNB PWR_2D5V_SVIN PWR_DDR_BT1 PWR_RT9624F_SNB1 PWR_RT9624F_SNB1A PWR_RT9624F_SNB2 PWR_RT9624F_SNB2A PWR_RT9624F_SNB3 PWR_RT9624F_SNB4 PWR_VCCSA_BOOT PWR_VCCSA_BOOT_R PWRRT9624F_BST3 PWRRT9624F_BST4
net group PWM_25_20: nets PWR_+0P95V_LGATE PWR_+0P95V_UG_R PWR_+0P95V_UGATE PWR_+PCH_1V0_LGATE PWR_+PCH_1V0_UG1 PWR_+PCH_1V0_UGATE PWR_+VCORE_VIN PWR_+VGT_VIN PWR_RT9624F_DRVH1 PWR_RT9624F_DRVH1A PWR_RT9624F_DRVH2 PWR_RT9624F_DRVH2A PWR_RT9624F_DRVH3 PWR_RT9624F_DRVH4 PWR_RT9624F_DRVL1 PWR_RT9624F_DRVL2 PWR_RT9624F_DRVL3 PWR_RT9624F_DRVL4 PWR_RT9624F_DRVLA1 PWR_RT9624F_DRVLA2 PWR_RT9624F_H1R PWR_RT9624F_H2R PWR_RT9624F_H3R PWR_RT9624F_H4R PWR_RT9624F_HR1A PWR_RT9624F_HR2A PWR_RT9624F_VCC1 PWR_RT9624F_VCC1A PWR_RT9624F_VCC2 PWR_RT9624F_VCC2A PWR_RT9624F_VCC3 PWR_RT9624F_VCC4 PWR_VCCSA_LG PWR_VCCSA_UG PWR_VCCSA_UG_R PWR_VDDQ_DDR_LGATE PWR_VDDQ_DDR_UG1 PWR_VDDQ_DDR_UGATE
net group PWM_25_40: nets PWR_+0P95V_PHASE PWR_+PCH_1V0_PHASE PWR_RT9624F_SW1 PWR_RT9624F_SW1A PWR_RT9624F_SW2 PWR_RT9624F_SW2A PWR_RT9624F_SW3 PWR_RT9624F_SW4 PWR_VCCSA_LX PWR_VDDQ_DDR_PHASE
net group PWM_40_20: nets PWR_+1V2_DDR
net group PWR_+0P95V_FB: nets PWR_+0P95V_FB VCCIO_SENSE VCCIO_SENSE_1
net group PWRCTRL_4_8: nets VDDQ_BLEED
net group PWRGD_4_10: nets 3D3V_AUX_EN 3D3V_AUX_EN_12V 5V_AUX_EN 5V_AUX_EN_INV +5V_AUX_EN +5V_AUX_EN_12V DDR_VTT_CNTL DDR_VTT_CNTL_GATE EN_VCCSA PWR_2D5V_EN PWR_+PCH_1V0_EN PWR_VCCSA_EN VCCIO_3P3V_EN VCCIO_3P3V_EN_C VCCIO_12V_EN VCCIO_12V_EN_C VCCIO_EN VCCSA_PGOOD VDDQ_EN VDDQ_S3_PG VPP_EN VTT_EN
net group RTC_CLK: nets SUSCLK_PCH
net group SATA_RX_CON_N2: nets SATA_RX_C_N2 SATA_RX_CON_N2 SATA_RX_PCH_N2
net group SATA_RX_CON_N3: nets SATA_RX_C_N3 SATA_RX_CON_N3 SATA_RX_PCH_N3
net group SATA_RX_CON_N4: nets SATA_RX_C_N4 SATA_RX_CON_N4 SATA_RX_PCH_N4
net group SATA_RX_CON_N5: nets SATA_RX_C_N5 SATA_RX_CON_N5 SATA_RX_PCH_N5
net group SATA_RX_CON_P2: nets SATA_RX_C_P2 SATA_RX_CON_P2 SATA_RX_PCH_P2
net group SATA_RX_CON_P3: nets SATA_RX_C_P3 SATA_RX_CON_P3 SATA_RX_PCH_P3
net group SATA_RX_CON_P4: nets SATA_RX_C_P4 SATA_RX_CON_P4 SATA_RX_PCH_P4
net group SATA_RX_CON_P5: nets SATA_RX_C_P5 SATA_RX_CON_P5 SATA_RX_PCH_P5
net group SATA_TX_CON_N2: nets SATA_TX_C_N2 SATA_TX_CON_N2 SATA_TX_PCH_N2
net group SATA_TX_CON_N3: nets SATA_TX_C_N3 SATA_TX_CON_N3 SATA_TX_PCH_N3
net group SATA_TX_CON_N4: nets SATA_TX_C_N4 SATA_TX_CON_N4 SATA_TX_PCH_N4
net group SATA_TX_CON_N5: nets SATA_TX_C_N5 SATA_TX_CON_N5 SATA_TX_PCH_N5
net group SATA_TX_CON_P2: nets SATA_TX_C_P2 SATA_TX_CON_P2 SATA_TX_PCH_P2
net group SATA_TX_CON_P3: nets SATA_TX_C_P3 SATA_TX_CON_P3 SATA_TX_PCH_P3
net group SATA_TX_CON_P4: nets SATA_TX_C_P4 SATA_TX_CON_P4 SATA_TX_PCH_P4
net group SATA_TX_CON_P5: nets SATA_TX_C_P5 SATA_TX_CON_P5 SATA_TX_PCH_P5
net group SATAEX_CTRL: nets DAS/DSS# SATAEX_DET0 SATAEX_DET1 SATAEX_DET_CON SATAEX_DET_CON_R SATAEX_DEVSLP SATAEX_DEVSLP_CON
net group SIO_CTRL: nets BTN_OCL_N BTN_OCL_R BTN_OCL_SIO_N COPEN_N CTL1 CTL2 CTL3 CTRL0 HM_VCCP HM_VCCP_R ISO_DET KA20GATE KBRST# LAN_PWR_EN_SIO LDRQ# PCIRST1# PCIRST2# PLTRST*_SIO PM_SLP_S3#_3 PWM_LED_N_C PWROK3_1 PWROK3_1_R SIO_AUDIO_MUTE SIO_CLK_DB SIO_CTL1 SIO_DAT_DB SIO_EUP_M SIO_EUP_SELECT SIO_OCL_GREEN SIO_OCL_YELLOW SIO_OCL_YELLOW_R SIO_PCIRSTIN# SIO_PWRLED_N SIO_TUBRO_LED_N SIO_VCORE SIO_VDD_EN SIO_VIN1 SIO_VIN2 SIO_VIN3 SIO_VIN4 SIO_VIN5 SIO_VREF SIO_WRST# SPI_WP_PCH_R TURN_OFF_PWM
net group SIO_EC: nets SIO_CE_N SIO_HOLD# SIO_SCK SIO_SCK_R SIO_SI SIO_SO SIO_WP#
net group SMBUS: nets SMB_CLK_MAIN SMB_CLK_MINI SMB_CLK_RESUME SMB_DATA_MAIN SMB_DATA_MINI SMB_DATA_RESUME SMBC_R2 SMBD_R2 SML1CLK_PCH SML1DATA_PCH SMLINK0_CLK SMLINK0_DATA WLAN_CLK_CON WLAN_CLK_PCH WLAN_DAT_CON WLAN_DAT_PCH WLAN_RST_CON WLAN_RST_PCH
net group SPI_WP_PCH: nets SPI_WP_PCH SPI_WP_ROM SPI_WP_SW
net group TP: nets CATERR#_CPU CPU_K12_R_N CPU_L12_R_P RSVD_AB13 RSVD_K13 SKL_CNL_N SUS_WARNB SUSACK_N TP_3G16_JTAG1 TP_3G16_RSVD_A32 TP_3G16_RSVD_A33 TP_3G16_RSVD_A50 TP_3G16RSVD_A19 TP_3G18_RSVD_B30 TP_16PRSNT_B82 TP_CPU7 TP_CPU9 TP_CPU10 TP_CPU11 TP_CPU12 TP_CPU_AC37 TP_CPU_AC38 TP_CPU_AC40 TP_CPU_AV1 TP_CPU_AV39 TP_CPU_AW2 TP_CPU_AW38 TP_CPU_G14 TP_CPU_H11 TP_CPU_H12 TP_CPU_H14 TP_CPU_J7 TP_CPU_J8 TP_CPU_K8 TP_CPU_K12 TP_CPU_L8 TP_CPU_L12 TP_DIMM1_PIN1 TP_DIMM2_PIN1 TP_DIMM3_PIN1 TP_DIMM4_PIN1 TP_DIMM_12V TP_DIMM_12V1 TP_DIMM_12V2 TP_DIMM_12V3 TP_PCH_AN17 TP_PCH_AN29 TP_PCH_AN43 TP_PCH_AN44 TP_PCH_AR19 TP_PCH_AR22 TP_PCH_AR39 TP_PCH_AR45 TP_PCH_BD14 TP_PCH_N29 TP_PCH_N31 TP_PCH_P24 TP_PCH_P27 TP_PCH_P29 TP_PCH_P31 TP_PCH_R24 TP_PCH_R27 TP_PCH_U13 TP_PCH_W13 TP_SLP_S5
net group USB30_TX_CMC_N1: nets USB30_TX_CMC_N1 USB30_TX_CON_N1 USB30_TX_PCH_N1
net group USB30_TX_CMC_N2: nets USB30_TX_CMC_N2 USB30_TX_CON_N2 USB30_TX_PCH_N2
net group USB30_TX_CMC_N3: nets USB30_TX_CMC_N3 USB30_TX_CON_N3 USB30_TX_PCH_N3
net group USB30_TX_CMC_N4: nets USB30_TX_CMC_N4 USB30_TX_CON_N4 USB30_TX_PCH_N4
net group USB30_TX_CMC_N5: nets USB30_TX_CMC_N5 USB30_TX_CON_N5 USB30_TX_PCH_N5
net group USB30_TX_CMC_N6: nets USB30_TX_CMC_N6 USB30_TX_CON_N6 USB30_TX_PCH_N6
net group USB30_TX_CMC_P1: nets USB30_TX_CMC_P1 USB30_TX_CON_P1 USB30_TX_PCH_P1
net group USB30_TX_CMC_P2: nets USB30_TX_CMC_P2 USB30_TX_CON_P2 USB30_TX_PCH_P2
net group USB30_TX_CMC_P3: nets USB30_TX_CMC_P3 USB30_TX_CON_P3 USB30_TX_PCH_P3
net group USB30_TX_CMC_P4: nets USB30_TX_CMC_P4 USB30_TX_CON_P4 USB30_TX_PCH_P4
net group USB30_TX_CMC_P5: nets USB30_TX_CMC_P5 USB30_TX_CON_P5 USB30_TX_PCH_P5
net group USB30_TX_CMC_P6: nets USB30_TX_CMC_P6 USB30_TX_CON_P6 USB30_TX_PCH_P6
net group USB_COMP: nets USB2_VBUSSENSE
net group USB_CTRL: nets ENABLE_2540 F_USBEN F_USBEN2 F_WPWR_USBEN ILIM_SEL ILIM_SEL_R P2402OV_EN R_USBEN R_USBEN1 R_USBEN1_R R_USBEN2 TPS2540_ILIM0 TPS2540_ILIM1 USB20_OC_CR# USB20_OC_F1# USB20_OC_F2# USB20_OC_RJUSB# USB30_ID_PIN10 USB30_OC_H1# USB30_OC_H1#_R USB30_OC_P1# USB30_OC_P1#_R USB30_OC_P2# USB_F_D USB_F_EN
net group VCCSA_IO_SSENSE: nets VCCSA_IO_SSENSE VSS_VCCIO_SENSE_1 VSS_VCCIO_SSENSE VSS_VCCSA_SSENSE
net group XCLK_BIASREF: nets XCLK_BIASREF_PCH

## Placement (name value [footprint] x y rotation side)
ATX1  JWT-CONN24B-S1-GP  [C4201WV0-B2X12P]  225 188 90 top
ATX2  JWT-CONN4B-GP  [C4201WV0-2-2P]  54 235 180 top
AUDF1  JWT-CONN10D-SFP7-GP  [1E450400]  22.68 7.03 180 top
AUDR1  AUDIO-JK187-GP  [ABA-JAK-028-K03]  3.5 100 90 top
BT1  BAT-AAA-BAT-029-K01-GP-U  [AAA-BAT-029-K01]  95 32 270 top
BUZ1  HY-05LF-GP  [HY-11H394]  232 127 90 top
C2  SCD1U16V2KX-3GP  [C402H22]  144.93 224.43 0 top
C3  SCD1U16V2KX-3GP  [C402H22]  147.57 224.41 0 top
C5  SCD1U25V3KX-GP  [C603H36]  132.64 93.55 270 top
C6  SCD1U25V3KX-GP  [C603H36]  134.76 95.82 180 top
C9  SCD1U25V3KX-GP  [C603H36]  137.59 98.42 180 top
C11  SCD1U16V2KX-3GP  [C402H22]  130.1 120.88 45 top
C12  SCD1U16V2KX-3GP  [C402H22]  126.03 116.87 45 top
C13  SCD1U16V2KX-3GP  [C402H22]  128.93 119.66 45 top
C364  SC10U10V5KX-2GP  [C805H54]  237.2 182.55 90 top
C365  SCD1U16V2ZY-2GP  [C402H22]  237.36 183.98 90 top
C367  SC4D7U10V5ZY-3GP  [C805H54]  235.25 205.57 0 top
C371  SCD1U16V2KX-3GP  [C402H22]  233.05 210.96 270 top
C372  SCD1U16V2KX-3GP  [C402H22]  238.07 210.79 90 top
C420  SC1U6D3V2KX-GP  [C402H22]  116.57 36.54 180 top
C421  SC1U6D3V2KX-GP  [C402H22]  122.34 30.39 270 top
C422  SC1U6D3V2KX-GP  [C402H22]  125.29 30.6 270 top
C447  SCD1U16V2KX-3GP  [C402H22]  238.36 37.11 0 top
C467  SCD22U10V2KX-1GP  [C402H22]  112.16 65.18 270 top
C468  SCD22U10V2KX-1GP  [C402H22]  112.16 64.31 270 top
C469  SCD22U10V2KX-1GP  [C402H22]  112.17 61.4 270 top
C470  SCD22U10V2KX-1GP  [C402H22]  112.17 60.53 270 top
C471  SCD22U10V2KX-1GP  [C402H22]  112.18 57.62 270 top
C472  SCD22U10V2KX-1GP  [C402H22]  112.18 56.76 270 top
C473  SCD22U10V2KX-1GP  [C402H22]  112.19 53.86 270 top
C474  SCD22U10V2KX-1GP  [C402H22]  112.19 52.99 270 top
C475  SCD1U16V2KX-3GP  [C402H22]  98.58 67.71 270 top
C476  SCD1U16V2KX-3GP  [C402H22]  100.26 47.9 0 top
C707  SCD1U16V2KX-3DLGP  [C402H22]  225.3 220.47 270 top
C708  SC1U10V2KX-1DLGP  [C402H22]  217.42 213.79 180 top
C726  SCD1U16V2KX-3GP  [C402H22]  98.63 64.67 270 top
C727  SC1U10V2KX-1DLGP  [C402H22]  98.62 63.78 270 top
C728  SC10U10V5KX-2DLGP  [C805H50]  98.35 66.25 270 top
C729  SC10U10V5KX-2DLGP  [C805H50]  98.87 47.9 0 top
C773  SCD1U16V2KX-3DLGP  [C402H22]  226.44 216.03 90 top
C774  SCD1U16V2KX-3DLGP  [C402H22]  220.93 215.01 90 top
C775  SC1U10V2KX-1DLGP  [C402H22]  231.39 218.57 90 top
C1004  SC22U6D3V5MX-2GP  [C805H58]  120.68 167.46 180 top
C1005  SC22U6D3V5MX-2GP  [C805H58]  122.63 167.46 180 top
C1006  SC22U6D3V5MX-2GP  [C805H58]  124.59 167.46 180 top
C1007  SC22U6D3V5MX-2GP  [C805H58]  126.54 167.46 180 top
C1008  SC22U6D3V5MX-2GP  [C805H58]  128.5 167.46 180 top
C1009  SC22U6D3V5MX-2GP  [C805H58]  128.56 163.6 0 top
C1014  SC22U6D3V5MX-2GP  [C805H58]  126.59 163.6 0 top
C1015  SC22U6D3V5MX-2GP  [C805H58]  124.62 163.6 0 top
C1016  SC22U6D3V5MX-2GP  [C805H58]  122.65 163.6 0 top
C1017  SC22U6D3V5MX-2GP  [C805H58]  120.68 163.6 0 top
C1018  SC22U6D3V5MX-2GP  [C805H58]  126.59 159.82 0 top
C1019  SC22U6D3V5MX-2GP  [C805H58]  128.56 159.82 0 top
C1020  SC22U6D3V5MX-2GP  [C805H58]  128.56 163.6 180 bottom
C1025  SC22U6D3V5MX-2GP  [C805H58]  126.59 163.6 180 bottom
C1026  SC22U6D3V5MX-2GP  [C805H58]  124.62 163.6 180 bottom
C1027  SC22U6D3V5MX-2GP  [C805H58]  122.65 163.6 180 bottom
C1028  SC22U6D3V5MX-2GP  [C805H58]  120.68 163.6 180 bottom
C1030  SC22U6D3V5MX-2GP  [C805H58]  118.72 163.6 180 bottom
C1031  SC22U6D3V5MX-2GP  [C805H58]  118.75 159.82 180 bottom
C1032  SC22U6D3V5MX-2GP  [C805H58]  120.72 159.82 180 bottom
C1033  SC22U6D3V5MX-2GP  [C805H58]  122.69 159.82 180 bottom
C1034  SC22U6D3V5MX-2GP  [C805H58]  124.62 159.82 180 bottom
C1037  SC22U6D3V3MX-1-GP  [C603H40]  85.38 175.28 180 top
C1038  SC22U6D3V3MX-1-GP  [C603H40]  119.09 160.15 0 top
C1039  SC22U6D3V3MX-1-GP  [C603H40]  119.1 163.98 0 top
C1040  SC22U6D3V3MX-1-GP  [C603H40]  85.49 168.8 0 top
C1041  SC22U6D3V3MX-1-GP  [C603H40]  85.35 184.99 180 top
C1042  SC22U6D3V3MX-1-GP  [C603H40]  85.38 177.97 0 top
C1043  SC22U6D3V5MX-2GP  [C805H58]  126.59 159.82 180 bottom
C1044  SC22U6D3V5MX-2GP  [C805H58]  128.56 159.82 180 bottom
C1045  SC22U6D3V5MX-2GP  [C805H58]  120.68 159.82 0 top
C1046  SC22U6D3V5MX-2GP  [C805H58]  122.65 159.82 0 top
C1047  SC22U6D3V5MX-2GP  [C805H58]  124.62 159.82 0 top
C1048  SC22U6D3V5MX-2GP  [C805H58]  137.11 101.66 0 top
C1049  SC1U6D3V2KX-GP  [C402H22]  135.65 102.49 180 top
C1050  SC22U6D3V5MX-2GP  [C805H58]  190.16 181.48 180 top
C1051  SC22U6D3V5MX-2GP  [C805H58]  168.29 159.69 270 top
C1052  SC22U6D3V5MX-2GP  [C805H58]  190.16 172.36 0 top
C1053  SC22U6D3V5MX-2GP  [C805H58]  190.16 156.92 180 top
C1054  SC47U6D3V5MX-1-GP  [C805H54]  124.01 168.55 270 bottom
C1055  SC47U6D3V5MX-1-GP  [C805H54]  127.85 170.49 90 top
C1056  SC47U6D3V5MX-1-GP  [C805H54]  120.12 172.45 90 top
C1057  SC47U6D3V5MX-1-GP  [C805H54]  120.12 170.49 90 top
C1058  SC47U6D3V5MX-1-GP  [C805H54]  124 172.45 90 top
C1059  SC47U6D3V5MX-1-GP  [C805H54]  127.84 174.42 270 bottom
C1060  SC47U6D3V5MX-1-GP  [C805H54]  123.98 174.4 270 bottom
C1061  SC47U6D3V5MX-1-GP  [C805H54]  120.12 174.4 270 bottom
C1062  SC47U6D3V5MX-1-GP  [C805H54]  127.85 170.49 270 bottom
C1063  SC47U6D3V5MX-1-GP  [C805H54]  127.85 172.45 270 bottom
C1064  SC47U6D3V5MX-1-GP  [C805H54]  124 170.49 270 bottom
C1065  SC47U6D3V5MX-1-GP  [C805H54]  124 172.45 270 bottom
C1066  SC47U6D3V5MX-1-GP  [C805H54]  120.12 170.49 270 bottom
C1067  SC47U6D3V5MX-1-GP  [C805H54]  120.12 172.45 270 bottom
C1068  SC47U6D3V5MX-1-GP  [C805H54]  124 170.49 90 top
C1069  SC47U6D3V5MX-1-GP  [C805H54]  127.85 172.45 90 top
C1070  SC22U6D3V3MX-1-GP  [C603H40]  132.21 209.17 180 top
C1071  SC22U6D3V3MX-1-GP  [C603H40]  123.5 203.23 90 top
C1072  SC22U6D3V3MX-1-GP  [C603H40]  112.65 211.96 0 top
C1073  SC22U6D3V3MX-1-GP  [C603H40]  115.11 203.15 270 top
C1074  SC22U6D3V3MX-1-GP  [C603H40]  123.37 209.91 90 top
C1075  SC22U6D3V3MX-1-GP  [C603H40]  106.98 203.15 270 top
C1077  SC47U6D3V5MX-1-GP  [C805H54]  127.84 168.55 270 bottom
C1079  SC47U6D3V5MX-1-GP  [C805H54]  120.12 168.55 270 bottom
C1081  SC47U6D3V5MX-1-GP  [C805H54]  89.94 208.64 180 top
C1084  SC22U6D3V3MX-1-GP  [C603H40]  116.33 171.04 90 bottom
C1085  SC22U6D3V3MX-1-GP  [C603H40]  116.33 172.21 90 bottom
C1086  SC22U6D3V3MX-1-GP  [C603H40]  116.33 173.38 90 bottom
C1087  SC22U6D3V3MX-1-GP  [C603H40]  119.12 166.99 270 bottom
C1088  SC22U6D3V3MX-1-GP  [C603H40]  98.95 203.17 270 top
C1089  SC22U6D3V3MX-1-GP  [C603H40]  119.08 168.17 0 top
C1091  SC22U6D3V5MX-2GP  [C805H58]  190.28 149.38 0 top
C1092  SC22U6D3V5MX-2GP  [C805H58]  216.15 175.26 90 top
C1093  SC22U6D3V5MX-2GP  [C805H58]  216.15 165.1 90 top
C1095  SC22U6D3V5MX-2GP  [C805H58]  216.15 167.13 90 top
C1096  SC22U6D3V5MX-2GP  [C805H58]  216.15 169.16 90 top
C1097  SC22U6D3V5MX-2GP  [C805H58]  216.15 171.2 90 top
C1098  SC22U6D3V5MX-2GP  [C805H58]  216.15 173.23 90 top
C1099  SC22U6D3V3MX-1-GP  [C603H40]  123.48 155.79 180 top
C1100  SC22U6D3V3MX-1-GP  [C603H40]  124.68 155.79 180 top
C1101  SC1U10V2KX-1GP  [C402H22]  170.35 184.73 180 top
C1102  SC4D7U6D3V3KX-GP  [C603H36]  170.15 167.69 270 top
C1103  SCD1U16V2KX-3GP  [C402H22]  170.21 168.71 270 top
C1106  SC1U10V2KX-1GP  [C402H22]  189.97 216.99 0 top
C1107  SC1U10V2KX-1GP  [C402H22]  210.52 146.35 90 top
C1108  SC1U10V2KX-1GP  [C402H22]  211.35 178.59 90 top
C1109  SCD1U16V2KX-3GP  [C402H22]  209.09 174.45 0 top
C1110  SCD1U16V2KX-3GP  [C402H22]  208.97 157.94 180 top
C1111  SCD1U16V2KX-3GP  [C402H22]  210.52 150.06 90 top
C1112  SCD1U16V2KX-3GP  [C402H22]  190.03 133.87 0 top
C1113  SCD1U16V2KX-3GP  [C402H22]  189.71 145.16 180 top
C1122  SCD1U16V2KX-3GP  [C402H22]  189.64 111.05 180 top
C1123  SC2D2U10V2KX-GP  [C402H22]  190.58 111.07 180 top
C1124  SC22U6D3V3MX-1-GP  [C603H40]  121.56 157.38 90 top
C1125  SC22U6D3V3MX-1-GP  [C603H40]  121.56 156.21 90 top
C1126  SC22U6D3V3MX-1-GP  [C603H40]  121.56 155.05 90 top
C1127  SC22U6D3V3MX-1-GP  [C603H40]  125.89 155.79 180 top
C1128  SC22U6D3V3MX-1-GP  [C603H40]  127.07 155.79 180 top
C1129  SC22U6D3V5MX-2GP  [C805H58]  128.63 156.24 180 top
C1130  SCD1U16V2KX-3GP  [C402H22]  170.13 104.44 270 top
C1131  SCD1U16V2KX-3GP  [C402H22]  170.1 103.25 270 top
C1132  SCD1U16V2KX-3GP  [C402H22]  190.47 231.44 0 top
C1133  SC2D2U10V2KX-GP  [C402H22]  210.57 232.13 90 top
C1134  SCD022U16V2KX-3GP  [C402H22]  148.46 225.93 90 top
C1135  SCD1U16V2KX-3GP  [C402H22]  211.4 224.63 90 top
C1136  SC2D2U10V2KX-GP  [C402H22]  209.37 226.54 270 top
C1137  SCD1U16V2KX-3GP  [C402H22]  210.57 230.3 90 top
C1138  SCD1U16V2KX-3GP  [C402H22]  211.66 225.5 90 top
C1139  SC2D2U10V2KX-GP  [C402H22]  189.56 231.44 0 top
C1140  SCD1U16V2KX-3GP  [C402H22]  209.4 224.56 270 top
C1141  SCD1U16V2KX-3GP  [C402H22]  210.57 231.22 90 top
C1142  SC2D2U10V2KX-GP  [C402H22]  209.38 225.56 270 top
C1143  SCD1U16V2KX-3GP  [C402H22]  189.62 184.89 180 top
C1144  SCD1U16V2KX-3GP  [C402H22]  170.87 186.14 270 top
C1145  SCD1U16V2KX-3GP  [C402H22]  190.54 184.86 180 top
C1146  SCD1U16V2KX-3GP  [C402H22]  170.85 187.04 270 top
C1201  SC1U10V2KX-1GP  [C402H22]  210.52 149.12 90 top
C1202  SCD1U16V2KX-3GP  [C402H22]  211.48 218.09 270 top
C1203  SCD1U16V2KX-3GP  [C402H22]  209.96 220.58 180 top
C1204  SCD1U25V3KX-GP  [C603H36]  211.74 223.57 90 top
C1205  SCD1U25V3KX-GP  [C603H36]  211.74 222.32 90 top
C1206  SCD022U16V2KX-3GP  [C402H22]  145.49 225.91 90 top
C1207  SC4D7U6D3V3KX-GP  [C603H36]  190.79 168.54 180 top
C1208  SCD1U16V2KX-3GP  [C402H22]  189.4 168.86 180 top
C1209  SC1U10V2KX-1GP  [C402H22]  210.52 147.24 90 top
C1210  SC1U10V2KX-1GP  [C402H22]  211.13 165.23 270 top
C1211  SC1U10V2KX-1GP  [C402H22]  213.59 177.36 180 top
C1212  SCD1U16V2KX-3GP  [C402H22]  210.52 148.18 90 top
C1213  SCD1U16V2KX-3GP  [C402H22]  210.21 139.67 90 top
C1214  SCD1U16V2KX-3GP  [C402H22]  211.39 181.5 90 top
C1215  SCD1U16V2KX-3GP  [C402H22]  170.75 148.95 270 top
C1216  SCD1U16V2KX-3GP  [C402H22]  211.13 164.34 270 top
C1217  SCD1U16V2KX-3GP  [C402H22]  193.34 80.16 0 top
C1218  SC2D2U10V2KX-GP  [C402H22]  194.46 86.41 180 top
C1219  SCD1U16V2KX-3GP  [C402H22]  170.08 101.65 270 top
C1220  SCD1U16V2KX-3GP  [C402H22]  170.08 100.76 270 top
C1301  SC1U10V2KX-1GP  [C402H22]  190.03 115.96 0 top
C1302  SC1U10V2KX-1GP  [C402H22]  190.03 207.53 0 top
C1303  SC1U10V2KX-1GP  [C402H22]  190.03 125.23 0 top
C1304  SC1U10V2KX-1GP  [C402H22]  169.45 162.38 180 top
C1305  SCD1U16V2KX-3GP  [C402H22]  170.59 153.57 270 top
C1306  SCD1U16V2KX-3GP  [C402H22]  170.7 176.83 270 top
C1307  SCD1U16V2KX-3GP  [C402H22]  189.76 228.02 180 top
C1308  SCD1U16V2KX-3GP  [C402H22]  209.02 219.58 180 top
C1309  SCD1U16V2KX-3GP  [C402H22]  209.55 201.04 180 top
C1310  SC4D7U6D3V3KX-GP  [C603H36]  210.49 168.66 180 top
C1311  SCD1U16V2KX-3GP  [C402H22]  209.4 168.63 180 top
C1312  SCD1U16V2KX-3GP  [C402H22]  193.57 86.41 180 top
C1313  SC2D2U10V2KX-GP  [C402H22]  192.68 86.41 180 top
C1314  SCD1U16V2KX-3GP  [C402H22]  190.63 108.08 180 top
C1315  SCD1U16V2KX-3GP  [C402H22]  189.61 108.08 180 top
C1401  SC1U10V2KX-1GP  [C402H22]  190.65 197.98 0 top
C1404  SC1U10V2KX-1GP  [C402H22]  169.15 152.5 270 top
C1405  SC1U10V2KX-1GP  [C402H22]  210.49 171.53 0 top
C1406  SC1U10V2KX-1GP  [C402H22]  190.7 228.02 180 top
C1407  SCD1U16V2KX-3GP  [C402H22]  189.76 197.97 0 top
C1408  SCD1U16V2KX-3GP  [C402H22]  210.24 157.89 180 top
C1409  SCD1U16V2KX-3GP  [C402H22]  190.63 145.16 180 top
C1410  SCD1U16V2KX-3GP  [C402H22]  190.03 190 0 top
C1411  SCD1U16V2KX-3GP  [C402H22]  209.17 117.09 90 top
C1412  SC4D7U6D3V3KX-GP  [C603H36]  190.79 165.17 0 top
C1413  SCD1U16V2KX-3GP  [C402H22]  189.4 164.86 0 top
C1414  SCD1U16V2KX-3GP  [C402H22]  202.39 83.07 90 top
C1415  SC2D2U10V2KX-GP  [C402H22]  202.39 83.96 90 top
C1416  SCD1U16V2KX-3GP  [C402H22]  190.58 103.02 0 top
C1417  SCD1U16V2KX-3GP  [C402H22]  189.56 103.02 0 top
C1601  SCD22U16V2KX-GP  [C402H22]  162.3 98.94 90 top
C1602  SCD1U16V2KX-3GP  [C402H22]  30.54 79.41 270 top
C1603  SCD1U16V2KX-3GP  [C402H22]  26.93 78.48 0 top
C1604  SCD22U16V2KX-GP  [C402H22]  62.49 46.64 180 top
C1605  SCD1U16V2KX-3GP  [C402H22]  30.54 80.3 270 top
C1606  SCD22U16V2KX-GP  [C402H22]  162.3 98.05 90 top
C1607  SCD22U16V2KX-GP  [C402H22]  63.38 46.64 180 top
C1608  SCD1U16V2KX-3GP  [C402H22]  27.82 78.48 0 top
C1617  SCD22U16V2KX-GP  [C402H22]  61.84 26.33 180 top
C1618  SCD22U16V2KX-GP  [C402H22]  60.93 26.34 180 top
C1701  SC47P50V2JN-3GP  [C402H22]  131.54 42.94 0 top
C1801  SC4P50V2CN-GP  [C402H22]  145.14 31.83 270 top
C1802  SC8P50V2CN-3GP  [C402H22]  137.19 61.11 180 top
C1803  SC8P50V2CN-3GP  [C402H22]  137.19 59.18 0 top
C1804  SC4P50V2CN-GP  [C402H22]  147.05 31.82 90 top
C2001  SC1U6D3V2KX-GP  [C402H22]  143.17 26.22 90 top
C2002  SCD1U16V2KX-3GP  [C402H22]  131.83 32.17 0 top
C2003  SC1U6D3V2KX-GP  [C402H22]  168.67 39.61 0 top
C2004  SC1U6D3V2KX-GP  [C402H22]  168.91 36.55 180 top
C2006  SC1U6D3V2KX-GP  [C402H22]  182.42 7.52 90 top
C2007  SCD1U16V2KX-3GP  [C402H22]  151.3 23.45 0 top
C2008  SCD1U16V2KX-3GP  [C402H22]  127.46 40.44 180 top
C2038  SCD1U16V2ZY-2GP  [C402H22]  237.63 225.93 90 top
C2101  SCD1U16V2KX-3GP  [C402H22]  159.93 30.79 0 top
C2301  SC1U6D3V2KX-GP  [C402H22]  158.49 25.37 270 top
C2302  SC22U6D3V5MX-2GP  [C805H58]  170.46 59.78 90 top
C2303  SC22U6D3V5MX-2GP  [C805H58]  170.46 61.73 90 top
C2304  SC22U6D3V5MX-2GP  [C805H58]  139.64 42.19 90 bottom
C2305  SC22U6D3V5MX-2GP  [C805H58]  139.64 44.13 90 bottom
C2306  SC22U6D3V5MX-2GP  [C805H58]  142.51 53.16 180 bottom
C2307  SC22U6D3V5MX-2GP  [C805H58]  140.56 53.16 180 bottom
C2308  SCD1U16V2KX-3GP  [C402H22]  171.49 35.64 90 top
C2309  SCD1U16V2KX-3GP  [C402H22]  154.04 46.48 180 bottom
C2310  SCD1U16V2KX-3GP  [C402H22]  161.72 37.38 270 bottom
C2311  SCD1U16V2KX-3GP  [C402H22]  164.13 26.16 180 top
C2312  SCD1U16V2KX-3GP  [C402H22]  155.5 39.45 180 bottom
C2313  SCD1U16V2KX-3GP  [C402H22]  169.92 46.04 270 top
C2314  SCD1U16V2KX-3GP  [C402H22]  166.5 59.94 0 top
C2315  SCD1U16V2KX-3GP  [C402H22]  136.92 53.77 270 top
C2316  SCD1U16V2KX-3GP  [C402H22]  177.8 34.25 0 top
C2317  SCD1U16V2KX-3GP  [C402H22]  167.66 41.86 180 top
C2318  SCD1U16V2KX-3GP  [C402H22]  171.49 34.77 90 top
C2319  SCD1U16V2KX-3GP  [C402H22]  151.74 49.97 90 bottom
C2320  SCD1U16V2KX-3GP  [C402H22]  156.09 48.41 90 bottom
C2321  SCD1U16V2KX-3GP  [C402H22]  158.22 47.18 180 bottom
C2322  SCD1U16V2KX-3GP  [C402H22]  143.84 34.01 90 top
C2501  SC1U10V2KX-1GP  [C402H22]  188.94 26.89 90 top
C2503  SCD1U25V3KX-GP  [C603H36]  105.03 22.73 180 top
C2504  SCD1U16V2KX-3GP  [C402H22]  106.05 22.35 180 top
C2601  SC1U16V3KX-2GP  [C603H36]  217.47 225.76 0 top
C2602  SC1U25V5KX-1GP  [C805H58]  154.31 232.03 90 top
C2603  SCD1U16V2KX-3GP  [C402H22]  223.37 230.07 0 top
C2604  SC1U16V3KX-2GP  [C603H36]  231.77 48.12 90 top
C2605  SCD1U16V2KX-3GP  [C402H22]  236.15 145.31 0 top
C2712  SC22P50V2JN-4GP  [C402H22]  24.46 47.45 90 top
C2713  SCD1U16V2KX-3GP  [C402H22]  24.5 49.66 90 top
C2717  SCD1U25V3KX-GP  [C603H36]  8.07 24.76 90 top
C2718  SCD1U25V3KX-GP  [C603H36]  26.67 29.36 270 top
C2719  SCD1U25V3KX-GP  [C603H36]  6.35 41.89 90 top
C2720  SCD1U25V3KX-GP  [C603H36]  19.61 42.09 270 top
C2721  SCD1U16V2KX-3GP  [C402H22]  26.42 33.08 180 top
C2722  SC22U6D3V5MX-2GP  [C805H58]  27.87 33.02 180 top
C2723  SCD1U16V2KX-3GP  [C402H22]  27.16 35.25 90 top
C2724  SC10U10V5ZY-1GP  [C805H54]  9.49 55.75 270 top
C2725  SC10U10V5ZY-1GP  [C805H54]  10.66 43.28 0 top
C2726  SCD1U16V2KX-3GP  [C402H22]  9.39 54.34 270 top
C2727  SCD1U16V2KX-3GP  [C402H22]  12.88 42.16 270 top
C2728  SCD1U16V2KX-3GP  [C402H22]  25.88 43.43 0 top
C2729  SC10U10V5KX-2GP  [C805H54]  24.45 43.25 0 top
C2730  SC10U10V5KX-2GP  [C805H54]  8.56 50.07 270 top
C2731  SCD1U16V2KX-3GP  [C402H22]  8.92 48.66 270 top
C2732  SC10U10V5KX-2GP  [C805H54]  25.77 46.03 90 top
C2733  SC10U10V5KX-2GP  [C805H54]  8.56 52.03 270 top
C2734  SCD1U16V2KX-3GP  [C402H22]  9.39 53.45 270 top
C2735  SCD1U16V2KX-3GP  [C402H22]  14.72 41.33 0 top
C2736  SCD1U16V2KX-3GP  [C402H22]  16.69 41.34 0 top
C2912  SC1U10V2KX-1GP  [C402H22]  158.41 18.8 270 top
C2918  SC1U10V2KX-1GP  [C402H22]  43.23 10.04 270 top
C2919  SC1U10V2KX-1GP  [C402H22]  43.23 10.93 270 top
C2920  SCD1U16V2KX-3GP  [C402H22]  30.6 12.2 270 top
C2921  SCD1U16V2KX-3GP  [C402H22]  32.54 12.2 90 top
C2932  SC1KP50V2KX-1GP  [C402H22]  38.45 11.66 180 top
C2934  SC100P50V2JN-3GP  [C402H22]  19.14 11.66 270 top
C2935  SC100P50V2JN-3GP  [C402H22]  22.82 13.16 90 top
C2936  SC100P50V2JN-3GP  [C402H22]  17.18 11.66 90 top
C2937  SC100P50V2JN-3GP  [C402H22]  20.87 13.16 270 top
C3001  SC100P50V2JN-3GP  [C402H22]  17.53 68.53 270 top
C3002  SC100P50V2JN-3GP  [C402H22]  19.46 68.53 90 top
C3003  SC100P50V2JN-3GP  [C402H22]  11.71 67.21 270 top
C3004  SC100P50V2JN-3GP  [C402H22]  13.62 67.21 90 top
C3005  SC100P50V2JN-3GP  [C402H22]  6.09 67.1 270 top
C3006  SC100P50V2JN-3GP  [C402H22]  8 67.1 90 top
C3101  SC15P50V2JN-2-GP  [C402H22]  27.12 93.12 270 top
C3102  SC4D7U10V3KX-GP  [C603H36]  32.45 88.09 0 top
C3103  SCD1U16V2KX-3GP  [C402H22]  31.4 88.48 0 top
C3104  SCD1U16V2KX-3GP  [C402H22]  22.55 88.67 270 top
C3105  SCD1U16V2KX-3GP  [C402H22]  22.98 79.91 0 top
C3106  SCD1U16V2KX-3GP  [C402H22]  31.75 95.38 90 top
C3107  SCD1U16V2KX-3GP  [C402H22]  21.34 83.07 270 top
C3108  SC4D7U10V3KX-GP  [C603H36]  35.61 92.15 180 top
C3109  SCD1U16V2KX-3GP  [C402H22]  21.71 86.96 180 top
C3110  SCD1U16V2KX-3GP  [C402H22]  24.96 89.63 180 top
C3111  SCD1U16V2KX-3GP  [C402H22]  30.1 84.88 90 top
C3112  SCD1U16V2KX-3GP  [C402H22]  34.58 92.54 180 top
C3113  SCD1U16V2ZY-2GP  [C402H22]  30.58 82.27 90 top
C3114  SCD1U16V2KX-3GP  [C402H22]  30.1 85.75 90 top
C3115  SC1U16V3KX-2GP  [C603H36]  30.52 86.79 90 top
C3116  SC15P50V2JN-2-GP  [C402H22]  25.22 93.12 90 top
C3121  SCD1U16V2ZY-2GP  [C402H22]  34.1 83.59 90 top
C3123  SC4D7U10V3KX-GP  [C603H36]  22.18 90.46 0 top
C3124  SC4D7U10V3KX-GP  [C603H36]  24.01 79.66 0 top
C3140  SC4D7U10V3KX-GP  [C603H36]  37.78 97.59 90 top
C3141  SCD1U16V2KX-3GP  [C402H22]  35.24 101.52 270 top
C3142  SCD1U16V2KX-3GP  [C402H22]  79.43 45.9 180 top
C3143  SCD1U16V2KX-3GP  [C402H22]  80.19 36.7 270 top
C3201  SC1KP50V2KX-1GP  [C402H22]  28.5 100.27 270 top
C3202  SCD01U50V2KX-1GP  [C402H22]  27.72 102.03 0 top
C3204  SCD1U16V2KX-3GP  [C402H22]  29.17 127.2 90 top
C3205  SCD1U16V2KX-3GP  [C402H22]  32.15 104.96 0 top
C3206  SC1KP50V2KX-1GP  [C402H22]  30.5 100.27 90 top
C3207  SCD1U16V2KX-3GP  [C402H22]  29.17 128.09 90 top
C3401  SCD1U16V2KX-3GP  [C402H22]  79.35 30.32 90 top
C3402  SCD1U16V2KX-3GP  [C402H22]  77.38 39.79 0 top
C3403  SCD1U16V2KX-3GP  [C402H22]  79.35 29.43 90 top
C3504  SC1U10V3ZY-6GP  [C603H36]  214.62 95.36 270 top
C3506  SC1U10V3ZY-6GP  [C603H36]  214.99 93.07 90 top
C3507  SC1U10V3ZY-6GP  [C603H36]  220.58 92.86 90 top
C3508  SC4D7U6D3V3KX-GP  [C603H36]  212.47 98.55 0 top
C3509  SC1U10V3ZY-6GP  [C603H36]  211.33 101.35 0 top
C3510  SC1U10V3ZY-6GP  [C603H36]  188.8 83.19 270 top
C3511  SC1U10V3ZY-6GP  [C603H36]  191.49 83.19 270 top
C3601  SC1KP50V2KX-1GP  [C402H22]  29.73 124.67 180 top
C3605  SCD1U16V2KX-3GP  [C402H22]  16.26 135.46 180 top
C3606  SCD1U16V2KX-3GP  [C402H22]  17.15 135.47 180 top
C3701  SC1KP50V2KX-1GP  [C402H22]  95.1 9.64 180 top
C3702  SCD1U16V2KX-3GP  [C402H22]  97.64 10.15 270 top
C3703  SCD1U16V2KX-3GP  [C402H22]  108.78 11.26 90 top
C3704  SCD1U16V2KX-3GP  [C402H22]  89.02 8.75 90 top
C3705  SCD1U16V2KX-3GP  [C402H22]  84.71 8.65 270 top
C3706  SC1KP50V2KX-1GP  [C402H22]  82.24 9.14 0 top
C3708  SC22U16V6MX-GP  [C1206H71]  92.32 9.36 270 top
C3709  SC22U16V6MX-GP  [C1206H71]  120.04 14.33 180 top
C3710  SC22U16V6MX-GP  [C1206H71]  96.36 11.69 270 top
C3714  SCD1U16V2KX-3GP  [C402H22]  117.28 17.51 90 top
C3715  SC1KP50V2KX-1GP  [C402H22]  120.02 18.03 0 top
C3801  SC1KP50V2KX-1GP  [C402H22]  14.57 181.85 180 top
C3802  SCD1U16V2KX-3GP  [C402H22]  10.7 179.91 180 top
C3803  SC10U10V5KX-2GP  [C805H54]  13.12 180.53 180 top
C3804  SCD1U16V2KX-3GP  [C402H22]  11.33 156.47 180 top
C3805  SCD1U16V2KX-3GP  [C402H22]  9.82 179.9 180 top
C3806  SC10U10V5KX-2GP  [C805H54]  14.87 156.83 180 top
C3807  SCD1U16V2KX-3GP  [C402H22]  12.24 156.46 180 top
C3809  SC1U10V2KX-1GP  [C402H22]  8.26 154.18 90 top
C3810  SC1U10V2KX-1GP  [C402H22]  6.5 177.95 90 top
C3811  SC1U10V2KX-1GP  [C402H22]  7.72 182.65 90 top
C3812  SC1U10V2KX-1GP  [C402H22]  92.3 16.18 0 top
C3813  SC1U10V2KX-1GP  [C402H22]  118.97 6.76 180 top
C3901  SC1KP50V2KX-1GP  [C402H22]  125.03 20.82 90 top
C3902  SCD1U16V2KX-3GP  [C402H22]  129.39 17.85 90 top
C3903  SCD1U16V2KX-3GP  [C402H22]  149.82 19.72 180 top
C3904  SC22U16V6MX-GP  [C1206H71]  128.99 19.39 90 top
C4301  SC470P50V2KX-3GP  [C402H22]  218.19 195 270 top
C4302  SCD1U16V2KX-3GP  [C402H22]  233.11 177.9 0 top
C4303  SC470P50V2KX-3GP  [C402H22]  232.18 177.9 180 top
C4304  SCD1U16V2KX-3GP  [C402H22]  219.13 196.86 180 top
C4305  SCD1U16V2KX-3GP  [C402H22]  218.11 196.86 180 top
C4306  SCD1U16V2KX-3GP  [C402H22]  218.19 194.11 90 top
C4307  SCD1U25V3KX-GP  [C603H36]  47.6 235.61 0 top
C4308  SCD1U25V3KX-GP  [C603H36]  233.55 170.81 0 top
C4309  SCD1U25V3KX-GP  [C603H36]  233.43 166.88 180 top
C4310  SCD1U25V3KX-GP  [C603H36]  216.97 203.45 180 top
C4311  SCD1U25V3KX-GP  [C603H36]  217.17 189.1 0 top
C5601  SCD1U16V2KX-3GP  [C402H22]  25.81 217.63 270 top
C5602  SCD1U16V2KX-3GP  [C402H22]  25.82 211.95 270 top
C5603  SCD1U16V2KX-3GP  [C402H22]  25.82 212.84 270 top
C5604  SCD1U16V2KX-3GP  [C402H22]  25.81 214.34 270 top
C5605  SCD1U16V2KX-3GP  [C402H22]  25.81 215.23 270 top
C5606  SCD1U16V2KX-3GP  [C402H22]  25.81 216.74 270 top
C5607  SCD1U16V2KX-3GP  [C402H22]  25.81 219.2 270 top
C5608  SCD1U16V2KX-3GP  [C402H22]  25.81 220.09 270 top
C5609  SCD1U16V2KX-3GP  [C402H22]  19.05 234.04 0 top
C5610  SCD1U16V2KX-3GP  [C402H22]  14.53 228.83 0 top
C5611  SCD1U16V2KX-3GP  [C402H22]  24.09 226.08 270 top
C5612  SC470P50V2KX-3GP  [C402H22]  18.15 224.55 180 top
C5613  SC470P50V2KX-3GP  [C402H22]  18.13 222.59 0 top
C5701  SC470P50V2KX-3GP  [C402H22]  20.31 197.2 180 top
C5702  SCD1U16V2KX-3GP  [C402H22]  23.61 186.01 270 top
C5703  SCD1U16V2KX-3GP  [C402H22]  23.61 186.9 270 top
C5704  SCD1U16V2KX-3GP  [C402H22]  23.61 187.79 270 top
C5705  SCD1U16V2KX-3GP  [C402H22]  23.61 188.68 270 top
C5706  SCD1U16V2KX-3GP  [C402H22]  23.61 190.08 270 top
C5707  SCD1U16V2KX-3GP  [C402H22]  23.61 190.97 270 top
C5708  SCD1U16V2KX-3GP  [C402H22]  23.61 191.86 270 top
C5709  SCD1U16V2KX-3GP  [C402H22]  23.61 192.74 270 top
C5710  SCD1U16V2KX-3GP  [C402H22]  23.54 184.14 270 top
C5711  SCD1U16V2KX-3GP  [C402H22]  23.54 185.03 270 top
C5712  SC470P50V2KX-3GP  [C402H22]  14.89 204.84 90 top
C5713  SCD1U16V2KX-3GP  [C402H22]  14.89 205.73 90 top
C6002  SCD01U50V2KX-1GP  [C402H22]  220.93 39.04 0 top
C6003  SCD01U50V2KX-1GP  [C402H22]  221.84 39.04 0 top
C6004  SCD01U50V2KX-1GP  [C402H22]  221.89 25.17 0 top
C6005  SCD01U50V2KX-1GP  [C402H22]  220.95 25.17 0 top
C6006  SCD01U50V2KX-1GP  [C402H22]  221.74 33.3 0 top
C6007  SCD01U50V2KX-1GP  [C402H22]  220.83 33.3 0 top
C6008  SCD01U50V2KX-1GP  [C402H22]  221.87 18.54 0 top
C6009  SCD01U50V2KX-1GP  [C402H22]  220.98 18.54 0 top
C6010  SCD01U50V2KX-1GP  [C402H22]  211.2 41.02 0 top
C6011  SCD01U50V2KX-1GP  [C402H22]  211.68 35.32 90 top
C6012  SCD01U50V2KX-1GP  [C402H22]  211.68 36.44 90 top
C6013  SCD01U50V2KX-1GP  [C402H22]  210.19 41.02 0 top
C6014  SCD01U50V2KX-1GP  [C402H22]  211.62 26.09 0 top
C6015  SCD01U50V2KX-1GP  [C402H22]  211.84 19.94 90 top
C6016  SCD01U50V2KX-1GP  [C402H22]  211.84 20.83 90 top
C6017  SCD01U50V2KX-1GP  [C402H22]  210.69 26.11 0 top
C6110  SCD1U25V2KX-2-GP  [C402H22]  151.04 83.01 0 top
C6111  SC10U6D3V5KX-1GP  [C805H54]  149.52 82.25 0 top
C6112  SCD1U25V2KX-2-GP  [C402H22]  148.76 105.59 270 top
C6113  SCD1U25V2KX-2-GP  [C402H22]  148.77 104.63 270 top
C6214  SCD1U50V3KX-GP  [C603H36]  70.61 45.52 180 top
C6401  SC1KP50V2KX-1GP  [C402H22]  220.09 10.19 180 top
C6402  SC1U10V2KX-1GP  [C402H22]  211.35 10.46 90 top
C6403  SCD1U16V2KX-3GP  [C402H22]  198.68 16.43 90 top
C6404  SCD1U16V2KX-3GP  [C402H22]  185.14 12.63 90 top
C6405  SCD1U16V2KX-3GP  [C402H22]  188.72 11.68 90 top
C6406  SC1U10V2KX-1GP  [C402H22]  232.89 20.61 90 top
C7901  SC1U10V2KX-1GP  [C402H22]  228.36 51.85 0 top
C7902  SC1U10V2KX-1GP  [C402H22]  214.82 53.44 270 top
C7903  SC1U16V3KX-2GP  [C603H36]  209.2 67.48 270 top
C7904  SC100P50V2JN-3GP  [C402H22]  219.51 78.86 180 top
C7905  SC22U6D3V5MX-2GP  [C805H58]  236.86 51.99 0 top
C7906  SCD1U16V2ZY-2GP  [C402H22]  216.1 74.85 180 top
C7907  SC1U10V2KX-1GP  [C402H22]  235.42 52.82 0 top
C7908  SCD1U16V2ZY-2GP  [C402H22]  234.11 52.58 0 top
C7909  SCD1U16V2ZY-2GP  [C402H22]  209.47 74.7 90 top
C7911  SCD1U16V2ZY-2GP  [C402H22]  233.88 50.44 90 top
C7912  SCD1U16V2ZY-2GP  [C402H22]  230.93 49.21 270 top
C7913  SCD1U16V2ZY-2GP  [C402H22]  226.92 47.68 0 top
C7914  SCD1U16V2ZY-2GP  [C402H22]  227.81 47.68 0 top
C7915  SCD1U16V2ZY-2GP  [C402H22]  212.12 60.98 180 top
C7916  SCD1U16V2ZY-2GP  [C402H22]  232.74 73.64 270 top
C7917  SC22U6D3V5MX-2GP  [C805H58]  210.7 61.14 180 top
C7918  SC2D2U6D3V2MX-GP  [C402H22]  214.37 74.85 0 top
C7919  SCD1U16V2ZY-2GP  [C402H22]  215.24 74.85 180 top
C7920  SCD1U16V2ZY-2GP  [C402H22]  223.65 80.92 270 top
C7921  SCD1U16V2ZY-2GP  [C402H22]  221.88 44.81 270 top
C7925  SCD1U16V2ZY-2GP  [C402H22]  224.74 50.25 180 top
C7927  SCD1U16V2ZY-2GP  [C402H22]  228.02 50.34 90 top
C9302  SCD22U16V2KX-GP  [C402H22]  62.23 87.94 0 top
C9303  SCD22U16V2KX-GP  [C402H22]  61.21 87.94 0 top
C9304  SCD22U16V2KX-GP  [C402H22]  65.79 87.94 0 top
C9305  SCD22U16V2KX-GP  [C402H22]  64.78 87.94 0 top
C9306  SCD22U16V2KX-GP  [C402H22]  69.81 87.94 0 top
C9307  SCD22U16V2KX-GP  [C402H22]  68.79 87.94 0 top
C9308  SCD22U16V2KX-GP  [C402H22]  73.82 87.94 0 top
C9309  SCD22U16V2KX-GP  [C402H22]  72.8 87.94 0 top
C9310  SCD1U25V3KX-GP  [C603H36]  43.03 63.03 270 top
C9311  SCD1U25V3KX-GP  [C603H36]  43.03 64.22 270 top
C9312  SCD1U25V3KX-GP  [C603H36]  43.03 65.44 270 top
C9313  SCD22U16V2KX-GP  [C402H22]  79.79 87.94 0 top
C9314  SCD22U16V2KX-GP  [C402H22]  78.77 87.94 0 top
